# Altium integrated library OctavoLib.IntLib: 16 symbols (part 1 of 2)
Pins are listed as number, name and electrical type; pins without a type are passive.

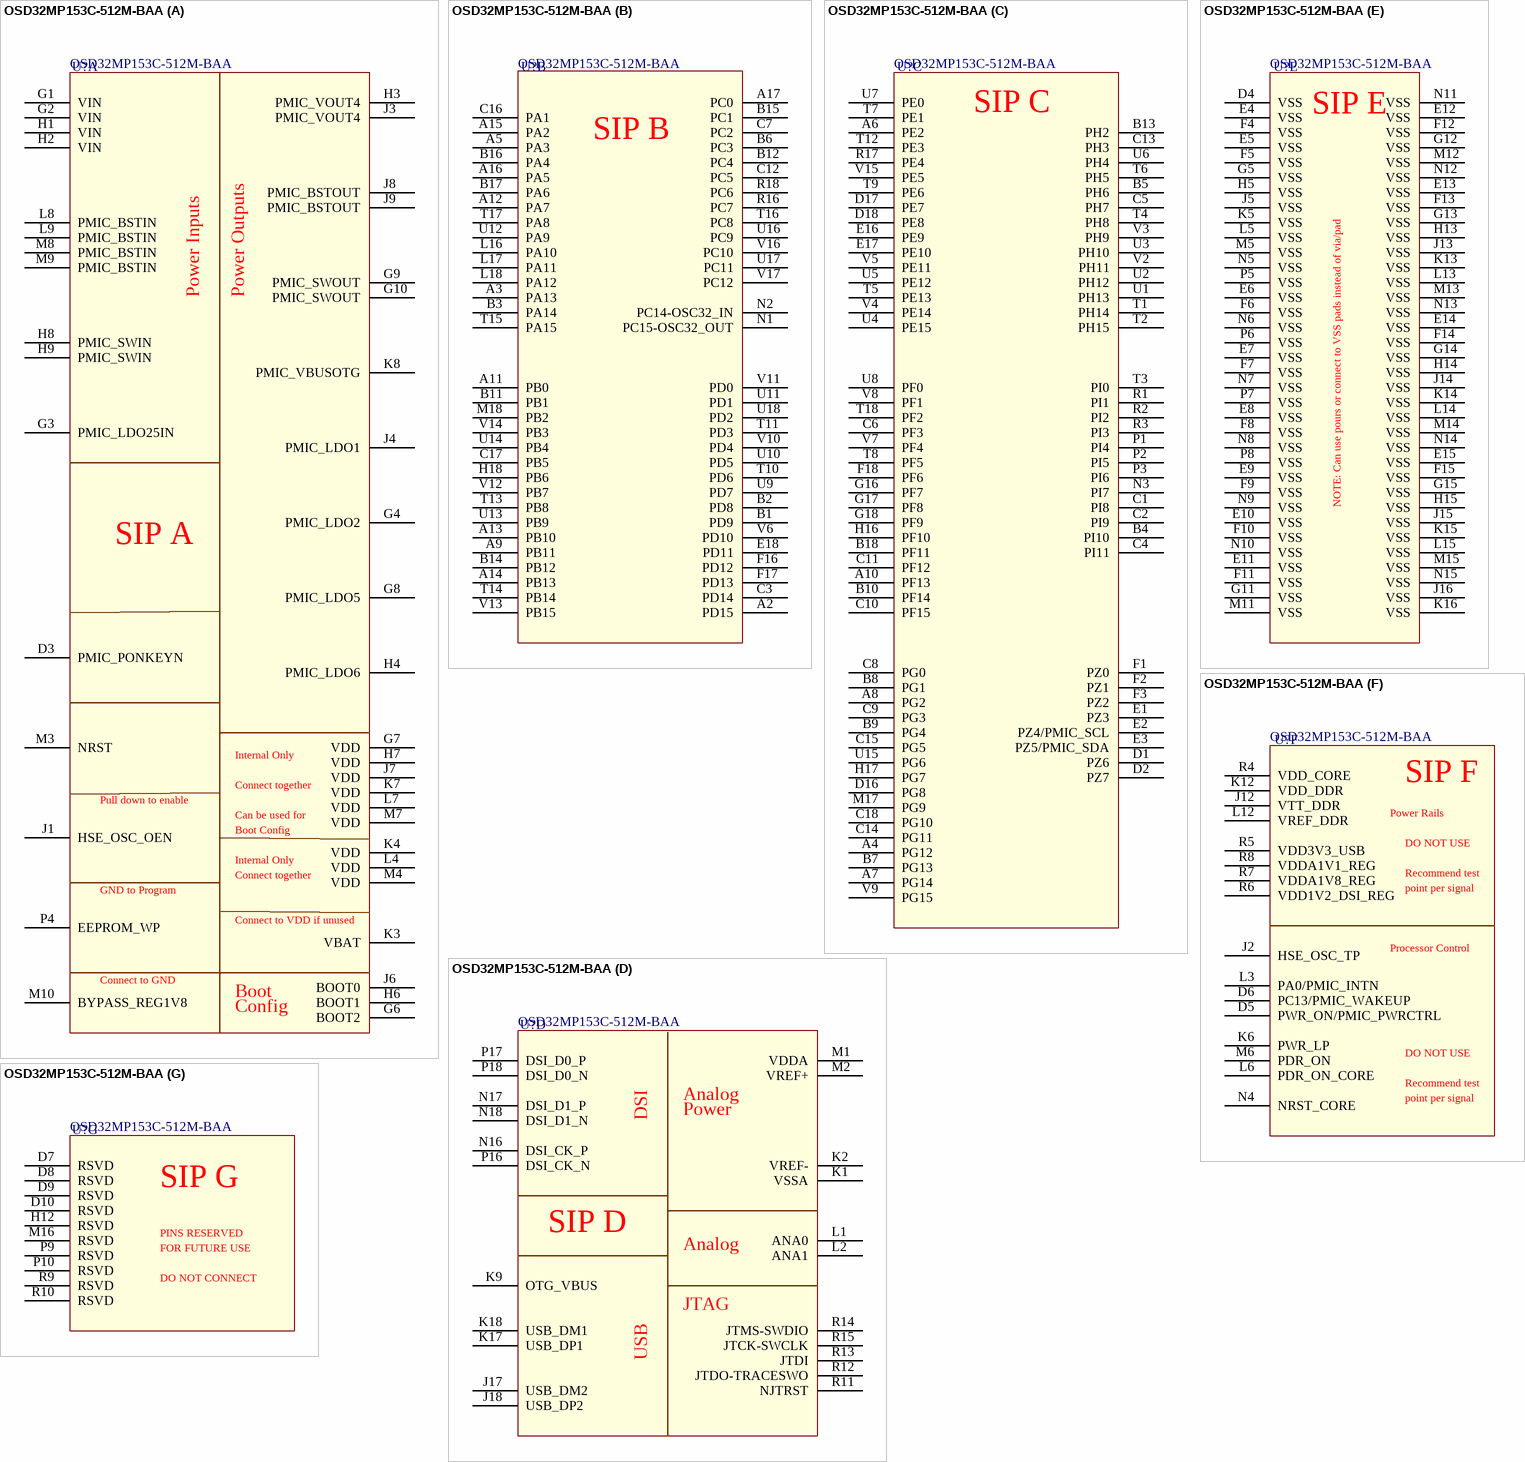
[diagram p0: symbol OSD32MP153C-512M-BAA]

## OSD32MP153C-512M-BAA
designator U?
Octavo Systems LLC OSD32MP15x Family SiP: 18mm x 18mm, 1mm pitch 302 pin BGA contains STM32MP153C, 512MB DDR3L, STPMIC1A, 4kB EEPROM, MEMS oscillators (24MHz) and passives. Commerical Temperature (case): 0C to 85C.
footprint BGA_18x18_302_1p00mm (302 pin 1mm pitch footprint)
part A pins: D3 PMIC_PONKEYN, G1 VIN, G2 VIN, G3 PMIC_LDO25IN, G4 PMIC_LDO2, G6 BOOT2, G7 VDD, G8 PMIC_LDO5, G9 PMIC_SWOUT, G10 PMIC_SWOUT, H1 VIN, H2 VIN, H3 PMIC_VOUT4, H4 PMIC_LDO6, H6 BOOT1, H7 VDD, H8 PMIC_SWIN, H9 PMIC_SWIN, J1 HSE_OSC_OEN, J3 PMIC_VOUT4, J4 PMIC_LDO1, J6 BOOT0, J7 VDD, J8 PMIC_BSTOUT, J9 PMIC_BSTOUT, K3 VBAT, K4 VDD, K7 VDD, K8 PMIC_VBUSOTG, L4 VDD, L7 VDD, L8 PMIC_BSTIN, L9 PMIC_BSTIN, M3 NRST, M4 VDD, M7 VDD, M8 PMIC_BSTIN, M9 PMIC_BSTIN, M10 BYPASS_REG1V8, P4 EEPROM_WP
part B pins: A2 PD15, A3 PA13, A5 PA3, A9 PB11, A11 PB0, A12 PA7, A13 PB10, A14 PB13, A15 PA2, A16 PA5, A17 PC0, B1 PD9, B2 PD8, B3 PA14, B6 PC3, B11 PB1, B12 PC4, B14 PB12, B15 PC1, B16 PA4, B17 PA6, C3 PD14, C7 PC2, C12 PC5, C16 PA1, C17 PB5, E18 PD11, F16 PD12, F17 PD13, H18 PB6, L16 PA10 "L16", L17 PA11, L18 PA12, M18 PB2, N1 PC15-OSC32_OUT, N2 PC14-OSC32_IN, R16 PC7, R18 PC6, T10 PD6, T11 PD3, T13 PB8, T14 PB14, T15 PA15, T16 PC8, T17 PA8, U9 PD7, U10 PD5, U11 PD1, U12 PA9, U13 PB9, U14 PB4, U16 PC9, U17 PC11, U18 PD2, V6 PD10, V10 PD4, V11 PD0, V12 PB7, V13 PB15, V14 PB3, V16 PC10, V17 PC12
part C pins: A4 PG12, A6 PE2, A7 PG14, A8 PG2, A10 PF13, B4 PI10, B5 PH6, B7 PG13, B8 PG1, B9 PG4, B10 PF14, B13 PH2, B18 PF11, C1 PI8, C2 PI9, C4 PI11, C5 PH7, C6 PF3, C8 PG0, C9 PG3, C10 PF15, C11 PF12, C13 PH3, C14 PG11, C15 PG5, C18 PG10, D1 PZ6, D2 PZ7, D16 PG8, D17 PE7, D18 PE8, E1 PZ3, E2 PZ4/PMIC_SCL, E3 PZ5/PMIC_SDA, E16 PE9, E17 PE10, F1 PZ0, F2 PZ1, F3 PZ2, F18 PF6, G16 PF7, G17 PF8, G18 PF9, H16 PF10, H17 PG7, M17 PG9, N3 PI7, P1 PI4, P2 PI5, P3 PI6, R1 PI1, R2 PI2, R3 PI3, R17 PE4, T1 PH14, T2 PH15, T3 PI0, T4 PH8, T5 PE13, T6 PH5, T7 PE1, T8 PF5, T9 PE6, T12 PE3, T18 PF2, U1 PH13, U2 PH12, U3 PH10, U4 PE15, U5 PE12, U6 PH4, U7 PE0, U8 PF0, U15 PG6, V2 PH11, V3 PH9, V4 PE14, V5 PE11, V7 PF4, V8 PF1, V9 PG15, V15 PE5
part D pins: J17 USB_DM2, J18 USB_DP2, K1 VSSA, K2 VREF-, K9 OTG_VBUS, K17 USB_DP1, K18 USB_DM1, L1 ANA0, L2 ANA1, M1 VDDA, M2 VREF+, N16 DSI_CK_P, N17 DSI_D1_P, N18 DSI_D1_N, P16 DSI_CK_N, P17 DSI_D0_P, P18 DSI_D0_N, R11 NJTRST, R12 JTDO-TRACESWO, R13 JTDI, R14 JTMS-SWDIO, R15 JTCK-SWCLK
part E pins: D4 VSS, E4 VSS, E5 VSS, E6 VSS, E7 VSS, E8 VSS, E9 VSS, E10 VSS, E11 VSS, E12 VSS, E13 VSS, E14 VSS, E15 VSS, F4 VSS, F5 VSS, F6 VSS, F7 VSS, F8 VSS, F9 VSS, F10 VSS, F11 VSS, F12 VSS, F13 VSS, F14 VSS, F15 VSS, G5 VSS, G11 VSS, G12 VSS, G13 VSS, G14 VSS, G15 VSS, H5 VSS, H13 VSS, H14 VSS, H15 VSS, J5 VSS, J13 VSS, J14 VSS, J15 VSS, J16 VSS, K5 VSS, K13 VSS, K14 VSS, K15 VSS, K16 VSS, L5 VSS, L13 VSS, L14 VSS, L15 VSS, M5 VSS, M11 VSS, M12 VSS, M13 VSS, M14 VSS, M15 VSS, N5 VSS, N6 VSS, N7 VSS, N8 VSS, N9 VSS, N10 VSS, N11 VSS, N12 VSS, N13 VSS, N14 VSS, N15 VSS, P5 VSS, P6 VSS, P7 VSS, P8 VSS
part F pins: D5 PWR_ON/PMIC_PWRCTRL, D6 PC13/PMIC_WAKEUP, J2 HSE_OSC_TP, J12 VTT_DDR, K6 PWR_LP, K12 VDD_DDR, L3 PA0/PMIC_INTN, L6 PDR_ON_CORE, L12 VREF_DDR, M6 PDR_ON, N4 NRST_CORE, R4 VDD_CORE, R5 VDD3V3_USB, R6 VDD1V2_DSI_REG, R7 VDDA1V8_REG, R8 VDDA1V1_REG
part G pins: D7 RSVD, D8 RSVD, D9 RSVD, D10 RSVD, H12 RSVD, M16 RSVD, P9 RSVD, P10 RSVD, R9 RSVD, R10 RSVD

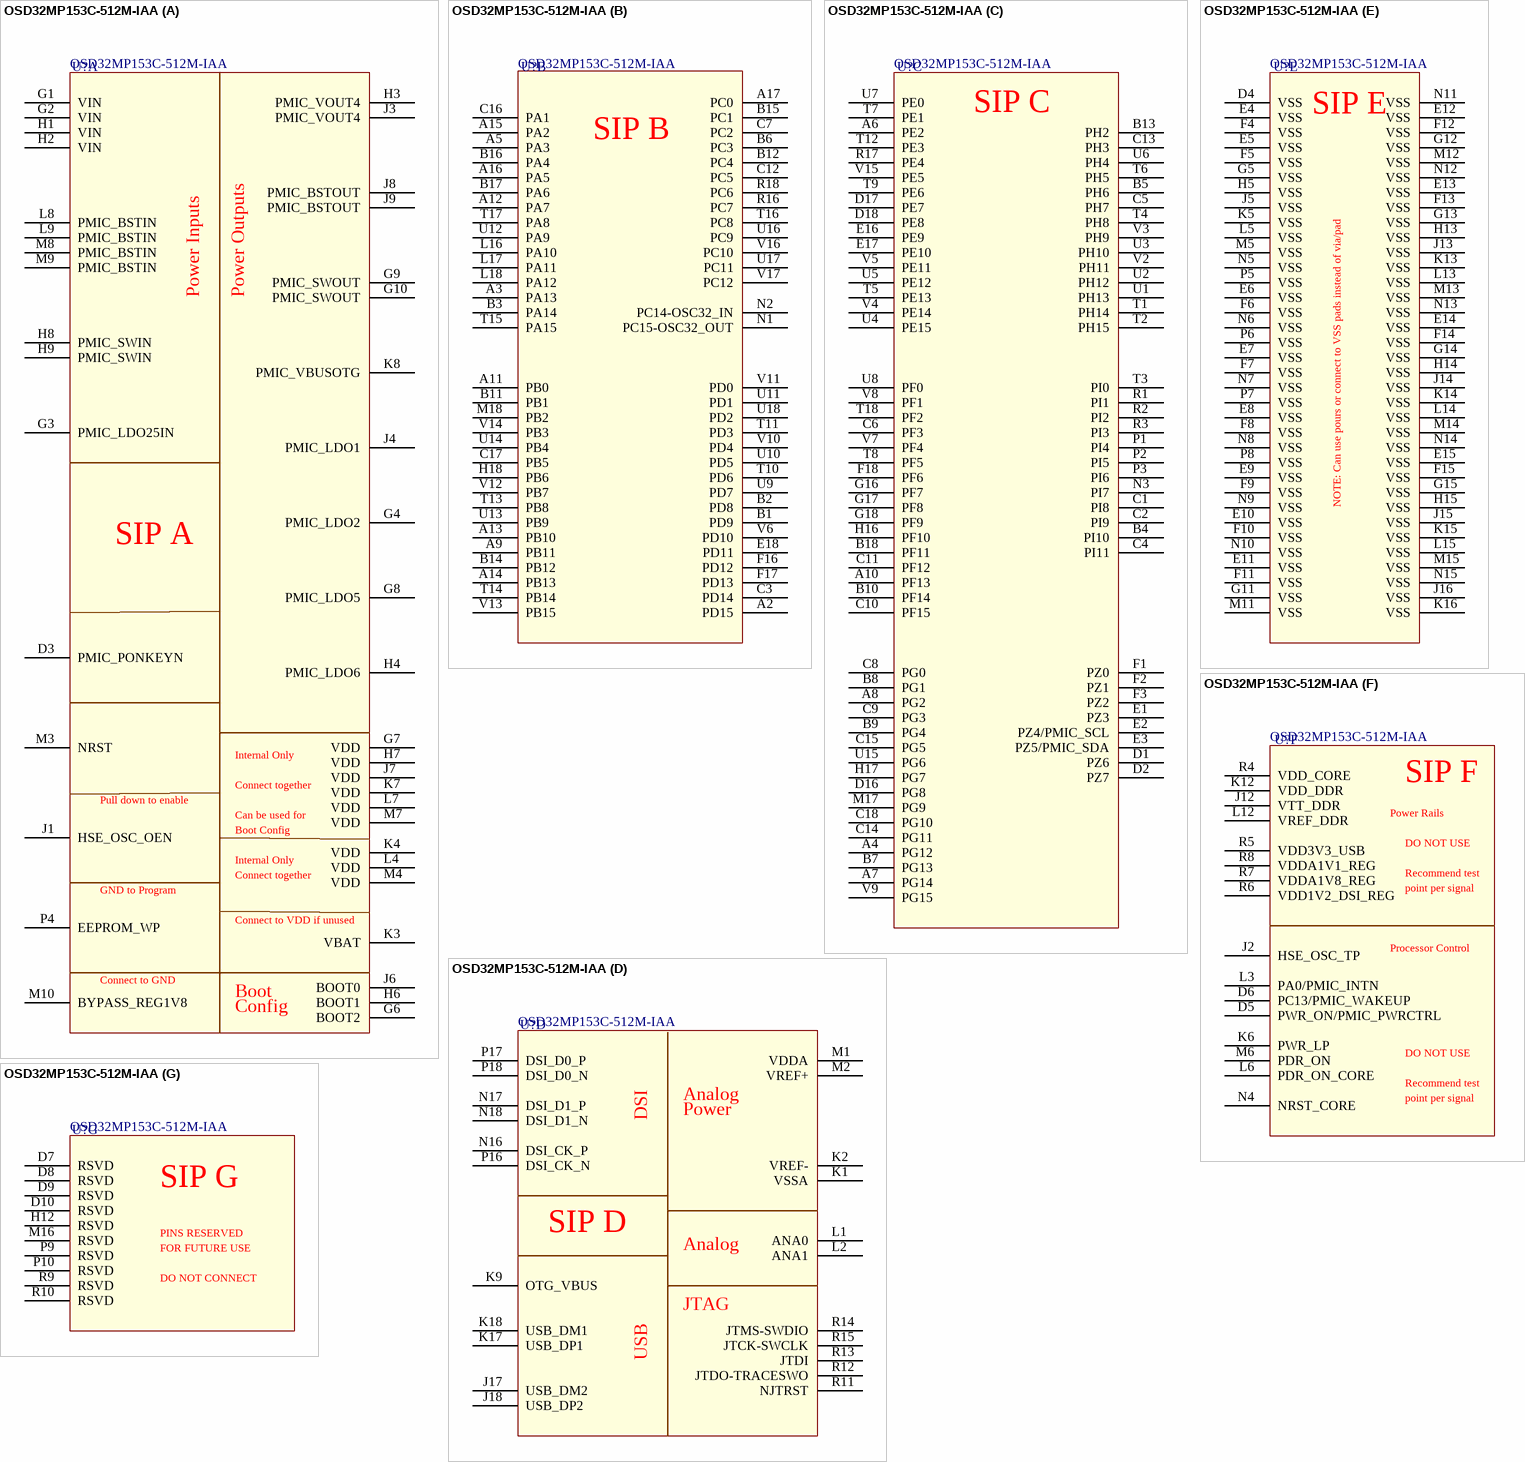
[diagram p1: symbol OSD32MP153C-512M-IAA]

## OSD32MP153C-512M-IAA
designator U?
Octavo Systems LLC OSD32MP15x Family SiP: 18mm x 18mm, 1mm pitch 302 pin BGA contains STM32MP153C, 512MB DDR3L, STPMIC1A, 4kB EEPROM, MEMS oscillators (24MHz) and passives. Industrial Temperature (case): -40C to 85C.
footprint BGA_18x18_302_1p00mm (302 pin 1mm pitch footprint)
part A pins: D3 PMIC_PONKEYN, G1 VIN, G2 VIN, G3 PMIC_LDO25IN, G4 PMIC_LDO2, G6 BOOT2, G7 VDD, G8 PMIC_LDO5, G9 PMIC_SWOUT, G10 PMIC_SWOUT, H1 VIN, H2 VIN, H3 PMIC_VOUT4, H4 PMIC_LDO6, H6 BOOT1, H7 VDD, H8 PMIC_SWIN, H9 PMIC_SWIN, J1 HSE_OSC_OEN, J3 PMIC_VOUT4, J4 PMIC_LDO1, J6 BOOT0, J7 VDD, J8 PMIC_BSTOUT, J9 PMIC_BSTOUT, K3 VBAT, K4 VDD, K7 VDD, K8 PMIC_VBUSOTG, L4 VDD, L7 VDD, L8 PMIC_BSTIN, L9 PMIC_BSTIN, M3 NRST, M4 VDD, M7 VDD, M8 PMIC_BSTIN, M9 PMIC_BSTIN, M10 BYPASS_REG1V8, P4 EEPROM_WP
part B pins: A2 PD15, A3 PA13, A5 PA3, A9 PB11, A11 PB0, A12 PA7, A13 PB10, A14 PB13, A15 PA2, A16 PA5, A17 PC0, B1 PD9, B2 PD8, B3 PA14, B6 PC3, B11 PB1, B12 PC4, B14 PB12, B15 PC1, B16 PA4, B17 PA6, C3 PD14, C7 PC2, C12 PC5, C16 PA1, C17 PB5, E18 PD11, F16 PD12, F17 PD13, H18 PB6, L16 PA10 "L16", L17 PA11, L18 PA12, M18 PB2, N1 PC15-OSC32_OUT, N2 PC14-OSC32_IN, R16 PC7, R18 PC6, T10 PD6, T11 PD3, T13 PB8, T14 PB14, T15 PA15, T16 PC8, T17 PA8, U9 PD7, U10 PD5, U11 PD1, U12 PA9, U13 PB9, U14 PB4, U16 PC9, U17 PC11, U18 PD2, V6 PD10, V10 PD4, V11 PD0, V12 PB7, V13 PB15, V14 PB3, V16 PC10, V17 PC12
part C pins: A4 PG12, A6 PE2, A7 PG14, A8 PG2, A10 PF13, B4 PI10, B5 PH6, B7 PG13, B8 PG1, B9 PG4, B10 PF14, B13 PH2, B18 PF11, C1 PI8, C2 PI9, C4 PI11, C5 PH7, C6 PF3, C8 PG0, C9 PG3, C10 PF15, C11 PF12, C13 PH3, C14 PG11, C15 PG5, C18 PG10, D1 PZ6, D2 PZ7, D16 PG8, D17 PE7, D18 PE8, E1 PZ3, E2 PZ4/PMIC_SCL, E3 PZ5/PMIC_SDA, E16 PE9, E17 PE10, F1 PZ0, F2 PZ1, F3 PZ2, F18 PF6, G16 PF7, G17 PF8, G18 PF9, H16 PF10, H17 PG7, M17 PG9, N3 PI7, P1 PI4, P2 PI5, P3 PI6, R1 PI1, R2 PI2, R3 PI3, R17 PE4, T1 PH14, T2 PH15, T3 PI0, T4 PH8, T5 PE13, T6 PH5, T7 PE1, T8 PF5, T9 PE6, T12 PE3, T18 PF2, U1 PH13, U2 PH12, U3 PH10, U4 PE15, U5 PE12, U6 PH4, U7 PE0, U8 PF0, U15 PG6, V2 PH11, V3 PH9, V4 PE14, V5 PE11, V7 PF4, V8 PF1, V9 PG15, V15 PE5
part D pins: J17 USB_DM2, J18 USB_DP2, K1 VSSA, K2 VREF-, K9 OTG_VBUS, K17 USB_DP1, K18 USB_DM1, L1 ANA0, L2 ANA1, M1 VDDA, M2 VREF+, N16 DSI_CK_P, N17 DSI_D1_P, N18 DSI_D1_N, P16 DSI_CK_N, P17 DSI_D0_P, P18 DSI_D0_N, R11 NJTRST, R12 JTDO-TRACESWO, R13 JTDI, R14 JTMS-SWDIO, R15 JTCK-SWCLK
part E pins: D4 VSS, E4 VSS, E5 VSS, E6 VSS, E7 VSS, E8 VSS, E9 VSS, E10 VSS, E11 VSS, E12 VSS, E13 VSS, E14 VSS, E15 VSS, F4 VSS, F5 VSS, F6 VSS, F7 VSS, F8 VSS, F9 VSS, F10 VSS, F11 VSS, F12 VSS, F13 VSS, F14 VSS, F15 VSS, G5 VSS, G11 VSS, G12 VSS, G13 VSS, G14 VSS, G15 VSS, H5 VSS, H13 VSS, H14 VSS, H15 VSS, J5 VSS, J13 VSS, J14 VSS, J15 VSS, J16 VSS, K5 VSS, K13 VSS, K14 VSS, K15 VSS, K16 VSS, L5 VSS, L13 VSS, L14 VSS, L15 VSS, M5 VSS, M11 VSS, M12 VSS, M13 VSS, M14 VSS, M15 VSS, N5 VSS, N6 VSS, N7 VSS, N8 VSS, N9 VSS, N10 VSS, N11 VSS, N12 VSS, N13 VSS, N14 VSS, N15 VSS, P5 VSS, P6 VSS, P7 VSS, P8 VSS
part F pins: D5 PWR_ON/PMIC_PWRCTRL, D6 PC13/PMIC_WAKEUP, J2 HSE_OSC_TP, J12 VTT_DDR, K6 PWR_LP, K12 VDD_DDR, L3 PA0/PMIC_INTN, L6 PDR_ON_CORE, L12 VREF_DDR, M6 PDR_ON, N4 NRST_CORE, R4 VDD_CORE, R5 VDD3V3_USB, R6 VDD1V2_DSI_REG, R7 VDDA1V8_REG, R8 VDDA1V1_REG
part G pins: D7 RSVD, D8 RSVD, D9 RSVD, D10 RSVD, H12 RSVD, M16 RSVD, P9 RSVD, P10 RSVD, R9 RSVD, R10 RSVD

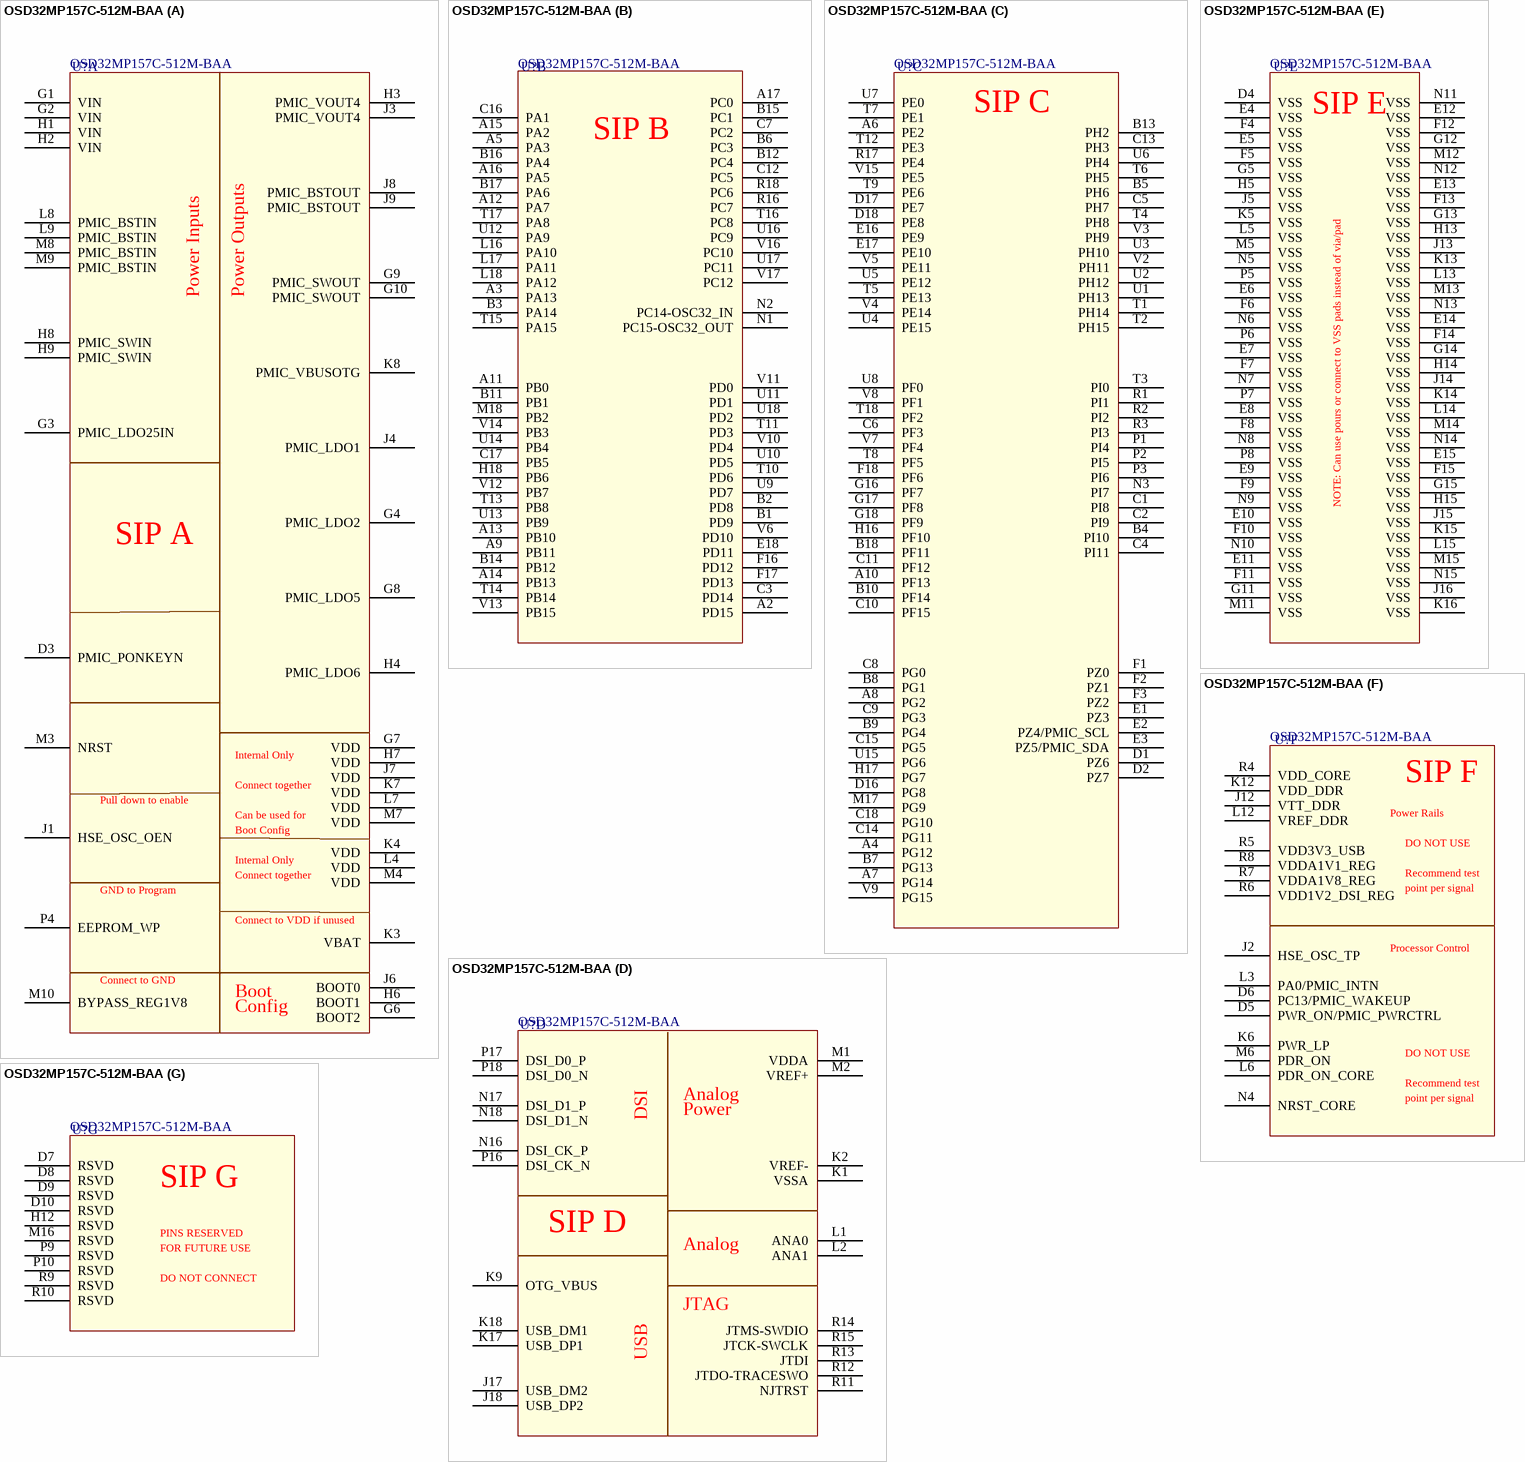
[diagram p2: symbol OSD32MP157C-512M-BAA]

## OSD32MP157C-512M-BAA
designator U?
Octavo Systems LLC OSD32MP15x Family SiP: 18mm x 18mm, 1mm pitch 302 pin BGA contains STM32MP157C, 512MB DDR3L, STPMIC1A, 4kB EEPROM, MEMS oscillators (24MHz) and passives. Commerical Temperature (case): 0C to 85C.
footprint BGA_18x18_302_1p00mm (302 pin 1mm pitch footprint)
part A pins: D3 PMIC_PONKEYN, G1 VIN, G2 VIN, G3 PMIC_LDO25IN, G4 PMIC_LDO2, G6 BOOT2, G7 VDD, G8 PMIC_LDO5, G9 PMIC_SWOUT, G10 PMIC_SWOUT, H1 VIN, H2 VIN, H3 PMIC_VOUT4, H4 PMIC_LDO6, H6 BOOT1, H7 VDD, H8 PMIC_SWIN, H9 PMIC_SWIN, J1 HSE_OSC_OEN, J3 PMIC_VOUT4, J4 PMIC_LDO1, J6 BOOT0, J7 VDD, J8 PMIC_BSTOUT, J9 PMIC_BSTOUT, K3 VBAT, K4 VDD, K7 VDD, K8 PMIC_VBUSOTG, L4 VDD, L7 VDD, L8 PMIC_BSTIN, L9 PMIC_BSTIN, M3 NRST, M4 VDD, M7 VDD, M8 PMIC_BSTIN, M9 PMIC_BSTIN, M10 BYPASS_REG1V8, P4 EEPROM_WP
part B pins: A2 PD15, A3 PA13, A5 PA3, A9 PB11, A11 PB0, A12 PA7, A13 PB10, A14 PB13, A15 PA2, A16 PA5, A17 PC0, B1 PD9, B2 PD8, B3 PA14, B6 PC3, B11 PB1, B12 PC4, B14 PB12, B15 PC1, B16 PA4, B17 PA6, C3 PD14, C7 PC2, C12 PC5, C16 PA1, C17 PB5, E18 PD11, F16 PD12, F17 PD13, H18 PB6, L16 PA10 "L16", L17 PA11, L18 PA12, M18 PB2, N1 PC15-OSC32_OUT, N2 PC14-OSC32_IN, R16 PC7, R18 PC6, T10 PD6, T11 PD3, T13 PB8, T14 PB14, T15 PA15, T16 PC8, T17 PA8, U9 PD7, U10 PD5, U11 PD1, U12 PA9, U13 PB9, U14 PB4, U16 PC9, U17 PC11, U18 PD2, V6 PD10, V10 PD4, V11 PD0, V12 PB7, V13 PB15, V14 PB3, V16 PC10, V17 PC12
part C pins: A4 PG12, A6 PE2, A7 PG14, A8 PG2, A10 PF13, B4 PI10, B5 PH6, B7 PG13, B8 PG1, B9 PG4, B10 PF14, B13 PH2, B18 PF11, C1 PI8, C2 PI9, C4 PI11, C5 PH7, C6 PF3, C8 PG0, C9 PG3, C10 PF15, C11 PF12, C13 PH3, C14 PG11, C15 PG5, C18 PG10, D1 PZ6, D2 PZ7, D16 PG8, D17 PE7, D18 PE8, E1 PZ3, E2 PZ4/PMIC_SCL, E3 PZ5/PMIC_SDA, E16 PE9, E17 PE10, F1 PZ0, F2 PZ1, F3 PZ2, F18 PF6, G16 PF7, G17 PF8, G18 PF9, H16 PF10, H17 PG7, M17 PG9, N3 PI7, P1 PI4, P2 PI5, P3 PI6, R1 PI1, R2 PI2, R3 PI3, R17 PE4, T1 PH14, T2 PH15, T3 PI0, T4 PH8, T5 PE13, T6 PH5, T7 PE1, T8 PF5, T9 PE6, T12 PE3, T18 PF2, U1 PH13, U2 PH12, U3 PH10, U4 PE15, U5 PE12, U6 PH4, U7 PE0, U8 PF0, U15 PG6, V2 PH11, V3 PH9, V4 PE14, V5 PE11, V7 PF4, V8 PF1, V9 PG15, V15 PE5
part D pins: J17 USB_DM2, J18 USB_DP2, K1 VSSA, K2 VREF-, K9 OTG_VBUS, K17 USB_DP1, K18 USB_DM1, L1 ANA0, L2 ANA1, M1 VDDA, M2 VREF+, N16 DSI_CK_P, N17 DSI_D1_P, N18 DSI_D1_N, P16 DSI_CK_N, P17 DSI_D0_P, P18 DSI_D0_N, R11 NJTRST, R12 JTDO-TRACESWO, R13 JTDI, R14 JTMS-SWDIO, R15 JTCK-SWCLK
part E pins: D4 VSS, E4 VSS, E5 VSS, E6 VSS, E7 VSS, E8 VSS, E9 VSS, E10 VSS, E11 VSS, E12 VSS, E13 VSS, E14 VSS, E15 VSS, F4 VSS, F5 VSS, F6 VSS, F7 VSS, F8 VSS, F9 VSS, F10 VSS, F11 VSS, F12 VSS, F13 VSS, F14 VSS, F15 VSS, G5 VSS, G11 VSS, G12 VSS, G13 VSS, G14 VSS, G15 VSS, H5 VSS, H13 VSS, H14 VSS, H15 VSS, J5 VSS, J13 VSS, J14 VSS, J15 VSS, J16 VSS, K5 VSS, K13 VSS, K14 VSS, K15 VSS, K16 VSS, L5 VSS, L13 VSS, L14 VSS, L15 VSS, M5 VSS, M11 VSS, M12 VSS, M13 VSS, M14 VSS, M15 VSS, N5 VSS, N6 VSS, N7 VSS, N8 VSS, N9 VSS, N10 VSS, N11 VSS, N12 VSS, N13 VSS, N14 VSS, N15 VSS, P5 VSS, P6 VSS, P7 VSS, P8 VSS
part F pins: D5 PWR_ON/PMIC_PWRCTRL, D6 PC13/PMIC_WAKEUP, J2 HSE_OSC_TP, J12 VTT_DDR, K6 PWR_LP, K12 VDD_DDR, L3 PA0/PMIC_INTN, L6 PDR_ON_CORE, L12 VREF_DDR, M6 PDR_ON, N4 NRST_CORE, R4 VDD_CORE, R5 VDD3V3_USB, R6 VDD1V2_DSI_REG, R7 VDDA1V8_REG, R8 VDDA1V1_REG
part G pins: D7 RSVD, D8 RSVD, D9 RSVD, D10 RSVD, H12 RSVD, M16 RSVD, P9 RSVD, P10 RSVD, R9 RSVD, R10 RSVD

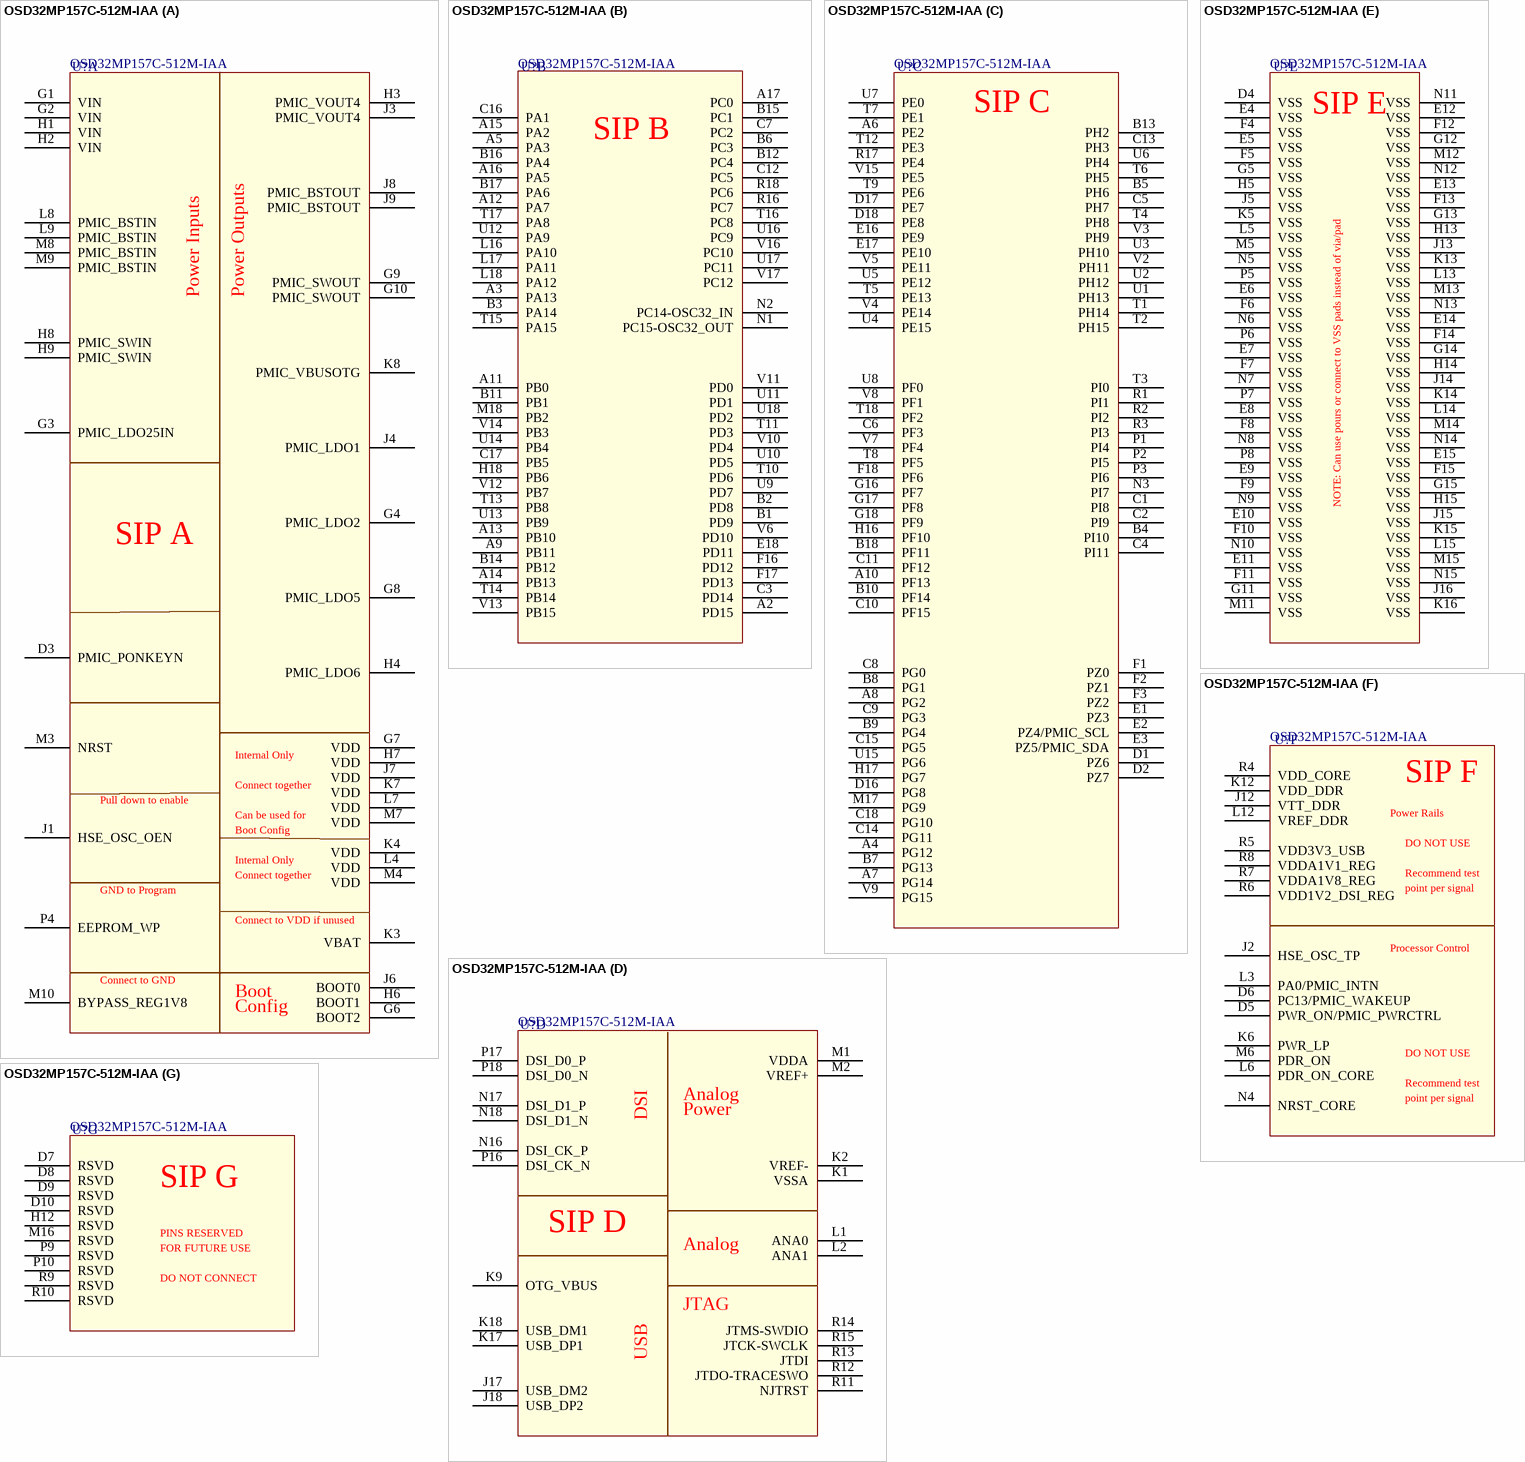
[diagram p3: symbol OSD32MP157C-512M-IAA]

## OSD32MP157C-512M-IAA
designator U?
Octavo Systems LLC OSD32MP15x Family SiP: 18mm x 18mm, 1mm pitch 302 pin BGA contains STM32MP157C, 512MB DDR3L, STPMIC1A, 4kB EEPROM, MEMS oscillators (24MHz) and passives. Industrial Temperature (case): -40C to 85C.
footprint BGA_18x18_302_1p00mm (302 pin 1mm pitch footprint)
part A pins: D3 PMIC_PONKEYN, G1 VIN, G2 VIN, G3 PMIC_LDO25IN, G4 PMIC_LDO2, G6 BOOT2, G7 VDD, G8 PMIC_LDO5, G9 PMIC_SWOUT, G10 PMIC_SWOUT, H1 VIN, H2 VIN, H3 PMIC_VOUT4, H4 PMIC_LDO6, H6 BOOT1, H7 VDD, H8 PMIC_SWIN, H9 PMIC_SWIN, J1 HSE_OSC_OEN, J3 PMIC_VOUT4, J4 PMIC_LDO1, J6 BOOT0, J7 VDD, J8 PMIC_BSTOUT, J9 PMIC_BSTOUT, K3 VBAT, K4 VDD, K7 VDD, K8 PMIC_VBUSOTG, L4 VDD, L7 VDD, L8 PMIC_BSTIN, L9 PMIC_BSTIN, M3 NRST, M4 VDD, M7 VDD, M8 PMIC_BSTIN, M9 PMIC_BSTIN, M10 BYPASS_REG1V8, P4 EEPROM_WP
part B pins: A2 PD15, A3 PA13, A5 PA3, A9 PB11, A11 PB0, A12 PA7, A13 PB10, A14 PB13, A15 PA2, A16 PA5, A17 PC0, B1 PD9, B2 PD8, B3 PA14, B6 PC3, B11 PB1, B12 PC4, B14 PB12, B15 PC1, B16 PA4, B17 PA6, C3 PD14, C7 PC2, C12 PC5, C16 PA1, C17 PB5, E18 PD11, F16 PD12, F17 PD13, H18 PB6, L16 PA10 "L16", L17 PA11, L18 PA12, M18 PB2, N1 PC15-OSC32_OUT, N2 PC14-OSC32_IN, R16 PC7, R18 PC6, T10 PD6, T11 PD3, T13 PB8, T14 PB14, T15 PA15, T16 PC8, T17 PA8, U9 PD7, U10 PD5, U11 PD1, U12 PA9, U13 PB9, U14 PB4, U16 PC9, U17 PC11, U18 PD2, V6 PD10, V10 PD4, V11 PD0, V12 PB7, V13 PB15, V14 PB3, V16 PC10, V17 PC12
part C pins: A4 PG12, A6 PE2, A7 PG14, A8 PG2, A10 PF13, B4 PI10, B5 PH6, B7 PG13, B8 PG1, B9 PG4, B10 PF14, B13 PH2, B18 PF11, C1 PI8, C2 PI9, C4 PI11, C5 PH7, C6 PF3, C8 PG0, C9 PG3, C10 PF15, C11 PF12, C13 PH3, C14 PG11, C15 PG5, C18 PG10, D1 PZ6, D2 PZ7, D16 PG8, D17 PE7, D18 PE8, E1 PZ3, E2 PZ4/PMIC_SCL, E3 PZ5/PMIC_SDA, E16 PE9, E17 PE10, F1 PZ0, F2 PZ1, F3 PZ2, F18 PF6, G16 PF7, G17 PF8, G18 PF9, H16 PF10, H17 PG7, M17 PG9, N3 PI7, P1 PI4, P2 PI5, P3 PI6, R1 PI1, R2 PI2, R3 PI3, R17 PE4, T1 PH14, T2 PH15, T3 PI0, T4 PH8, T5 PE13, T6 PH5, T7 PE1, T8 PF5, T9 PE6, T12 PE3, T18 PF2, U1 PH13, U2 PH12, U3 PH10, U4 PE15, U5 PE12, U6 PH4, U7 PE0, U8 PF0, U15 PG6, V2 PH11, V3 PH9, V4 PE14, V5 PE11, V7 PF4, V8 PF1, V9 PG15, V15 PE5
part D pins: J17 USB_DM2, J18 USB_DP2, K1 VSSA, K2 VREF-, K9 OTG_VBUS, K17 USB_DP1, K18 USB_DM1, L1 ANA0, L2 ANA1, M1 VDDA, M2 VREF+, N16 DSI_CK_P, N17 DSI_D1_P, N18 DSI_D1_N, P16 DSI_CK_N, P17 DSI_D0_P, P18 DSI_D0_N, R11 NJTRST, R12 JTDO-TRACESWO, R13 JTDI, R14 JTMS-SWDIO, R15 JTCK-SWCLK
part E pins: D4 VSS, E4 VSS, E5 VSS, E6 VSS, E7 VSS, E8 VSS, E9 VSS, E10 VSS, E11 VSS, E12 VSS, E13 VSS, E14 VSS, E15 VSS, F4 VSS, F5 VSS, F6 VSS, F7 VSS, F8 VSS, F9 VSS, F10 VSS, F11 VSS, F12 VSS, F13 VSS, F14 VSS, F15 VSS, G5 VSS, G11 VSS, G12 VSS, G13 VSS, G14 VSS, G15 VSS, H5 VSS, H13 VSS, H14 VSS, H15 VSS, J5 VSS, J13 VSS, J14 VSS, J15 VSS, J16 VSS, K5 VSS, K13 VSS, K14 VSS, K15 VSS, K16 VSS, L5 VSS, L13 VSS, L14 VSS, L15 VSS, M5 VSS, M11 VSS, M12 VSS, M13 VSS, M14 VSS, M15 VSS, N5 VSS, N6 VSS, N7 VSS, N8 VSS, N9 VSS, N10 VSS, N11 VSS, N12 VSS, N13 VSS, N14 VSS, N15 VSS, P5 VSS, P6 VSS, P7 VSS, P8 VSS
part F pins: D5 PWR_ON/PMIC_PWRCTRL, D6 PC13/PMIC_WAKEUP, J2 HSE_OSC_TP, J12 VTT_DDR, K6 PWR_LP, K12 VDD_DDR, L3 PA0/PMIC_INTN, L6 PDR_ON_CORE, L12 VREF_DDR, M6 PDR_ON, N4 NRST_CORE, R4 VDD_CORE, R5 VDD3V3_USB, R6 VDD1V2_DSI_REG, R7 VDDA1V8_REG, R8 VDDA1V1_REG
part G pins: D7 RSVD, D8 RSVD, D9 RSVD, D10 RSVD, H12 RSVD, M16 RSVD, P9 RSVD, P10 RSVD, R9 RSVD, R10 RSVD

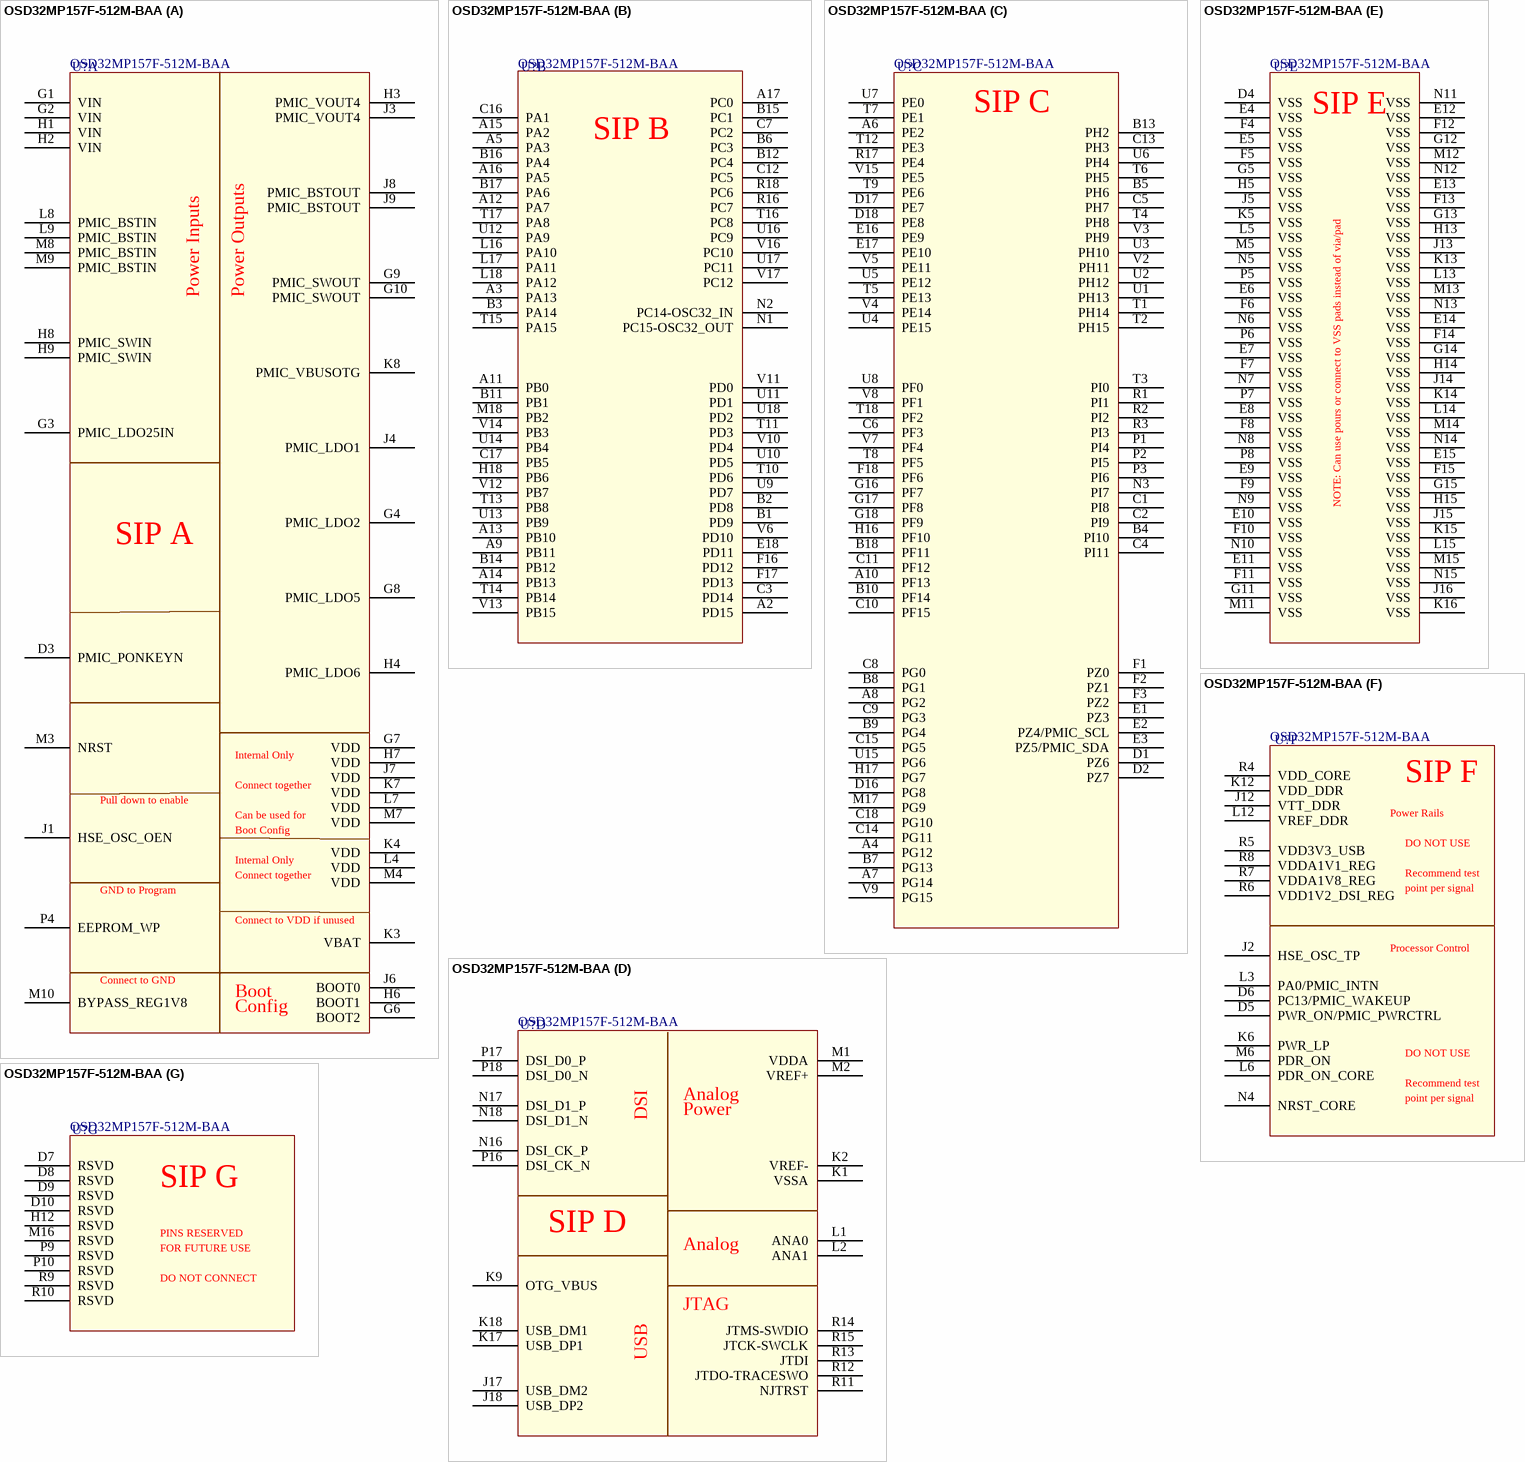
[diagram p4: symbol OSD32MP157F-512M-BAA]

## OSD32MP157F-512M-BAA
designator U?
Octavo Systems LLC OSD32MP15x Family SiP: 18mm x 18mm, 1mm pitch 302 pin BGA contains STM32MP157F, 512MB DDR3L, STPMIC1A, 4kB EEPROM, MEMS oscillators (24MHz) and passives. Commerical Temperature (case): 0C to 85C.
footprint BGA_18x18_302_1p00mm (302 pin 1mm pitch footprint)
part A pins: D3 PMIC_PONKEYN, G1 VIN, G2 VIN, G3 PMIC_LDO25IN, G4 PMIC_LDO2, G6 BOOT2, G7 VDD, G8 PMIC_LDO5, G9 PMIC_SWOUT, G10 PMIC_SWOUT, H1 VIN, H2 VIN, H3 PMIC_VOUT4, H4 PMIC_LDO6, H6 BOOT1, H7 VDD, H8 PMIC_SWIN, H9 PMIC_SWIN, J1 HSE_OSC_OEN, J3 PMIC_VOUT4, J4 PMIC_LDO1, J6 BOOT0, J7 VDD, J8 PMIC_BSTOUT, J9 PMIC_BSTOUT, K3 VBAT, K4 VDD, K7 VDD, K8 PMIC_VBUSOTG, L4 VDD, L7 VDD, L8 PMIC_BSTIN, L9 PMIC_BSTIN, M3 NRST, M4 VDD, M7 VDD, M8 PMIC_BSTIN, M9 PMIC_BSTIN, M10 BYPASS_REG1V8, P4 EEPROM_WP
part B pins: A2 PD15, A3 PA13, A5 PA3, A9 PB11, A11 PB0, A12 PA7, A13 PB10, A14 PB13, A15 PA2, A16 PA5, A17 PC0, B1 PD9, B2 PD8, B3 PA14, B6 PC3, B11 PB1, B12 PC4, B14 PB12, B15 PC1, B16 PA4, B17 PA6, C3 PD14, C7 PC2, C12 PC5, C16 PA1, C17 PB5, E18 PD11, F16 PD12, F17 PD13, H18 PB6, L16 PA10 "L16", L17 PA11, L18 PA12, M18 PB2, N1 PC15-OSC32_OUT, N2 PC14-OSC32_IN, R16 PC7, R18 PC6, T10 PD6, T11 PD3, T13 PB8, T14 PB14, T15 PA15, T16 PC8, T17 PA8, U9 PD7, U10 PD5, U11 PD1, U12 PA9, U13 PB9, U14 PB4, U16 PC9, U17 PC11, U18 PD2, V6 PD10, V10 PD4, V11 PD0, V12 PB7, V13 PB15, V14 PB3, V16 PC10, V17 PC12
part C pins: A4 PG12, A6 PE2, A7 PG14, A8 PG2, A10 PF13, B4 PI10, B5 PH6, B7 PG13, B8 PG1, B9 PG4, B10 PF14, B13 PH2, B18 PF11, C1 PI8, C2 PI9, C4 PI11, C5 PH7, C6 PF3, C8 PG0, C9 PG3, C10 PF15, C11 PF12, C13 PH3, C14 PG11, C15 PG5, C18 PG10, D1 PZ6, D2 PZ7, D16 PG8, D17 PE7, D18 PE8, E1 PZ3, E2 PZ4/PMIC_SCL, E3 PZ5/PMIC_SDA, E16 PE9, E17 PE10, F1 PZ0, F2 PZ1, F3 PZ2, F18 PF6, G16 PF7, G17 PF8, G18 PF9, H16 PF10, H17 PG7, M17 PG9, N3 PI7, P1 PI4, P2 PI5, P3 PI6, R1 PI1, R2 PI2, R3 PI3, R17 PE4, T1 PH14, T2 PH15, T3 PI0, T4 PH8, T5 PE13, T6 PH5, T7 PE1, T8 PF5, T9 PE6, T12 PE3, T18 PF2, U1 PH13, U2 PH12, U3 PH10, U4 PE15, U5 PE12, U6 PH4, U7 PE0, U8 PF0, U15 PG6, V2 PH11, V3 PH9, V4 PE14, V5 PE11, V7 PF4, V8 PF1, V9 PG15, V15 PE5
part D pins: J17 USB_DM2, J18 USB_DP2, K1 VSSA, K2 VREF-, K9 OTG_VBUS, K17 USB_DP1, K18 USB_DM1, L1 ANA0, L2 ANA1, M1 VDDA, M2 VREF+, N16 DSI_CK_P, N17 DSI_D1_P, N18 DSI_D1_N, P16 DSI_CK_N, P17 DSI_D0_P, P18 DSI_D0_N, R11 NJTRST, R12 JTDO-TRACESWO, R13 JTDI, R14 JTMS-SWDIO, R15 JTCK-SWCLK
part E pins: D4 VSS, E4 VSS, E5 VSS, E6 VSS, E7 VSS, E8 VSS, E9 VSS, E10 VSS, E11 VSS, E12 VSS, E13 VSS, E14 VSS, E15 VSS, F4 VSS, F5 VSS, F6 VSS, F7 VSS, F8 VSS, F9 VSS, F10 VSS, F11 VSS, F12 VSS, F13 VSS, F14 VSS, F15 VSS, G5 VSS, G11 VSS, G12 VSS, G13 VSS, G14 VSS, G15 VSS, H5 VSS, H13 VSS, H14 VSS, H15 VSS, J5 VSS, J13 VSS, J14 VSS, J15 VSS, J16 VSS, K5 VSS, K13 VSS, K14 VSS, K15 VSS, K16 VSS, L5 VSS, L13 VSS, L14 VSS, L15 VSS, M5 VSS, M11 VSS, M12 VSS, M13 VSS, M14 VSS, M15 VSS, N5 VSS, N6 VSS, N7 VSS, N8 VSS, N9 VSS, N10 VSS, N11 VSS, N12 VSS, N13 VSS, N14 VSS, N15 VSS, P5 VSS, P6 VSS, P7 VSS, P8 VSS
part F pins: D5 PWR_ON/PMIC_PWRCTRL, D6 PC13/PMIC_WAKEUP, J2 HSE_OSC_TP, J12 VTT_DDR, K6 PWR_LP, K12 VDD_DDR, L3 PA0/PMIC_INTN, L6 PDR_ON_CORE, L12 VREF_DDR, M6 PDR_ON, N4 NRST_CORE, R4 VDD_CORE, R5 VDD3V3_USB, R6 VDD1V2_DSI_REG, R7 VDDA1V8_REG, R8 VDDA1V1_REG
part G pins: D7 RSVD, D8 RSVD, D9 RSVD, D10 RSVD, H12 RSVD, M16 RSVD, P9 RSVD, P10 RSVD, R9 RSVD, R10 RSVD

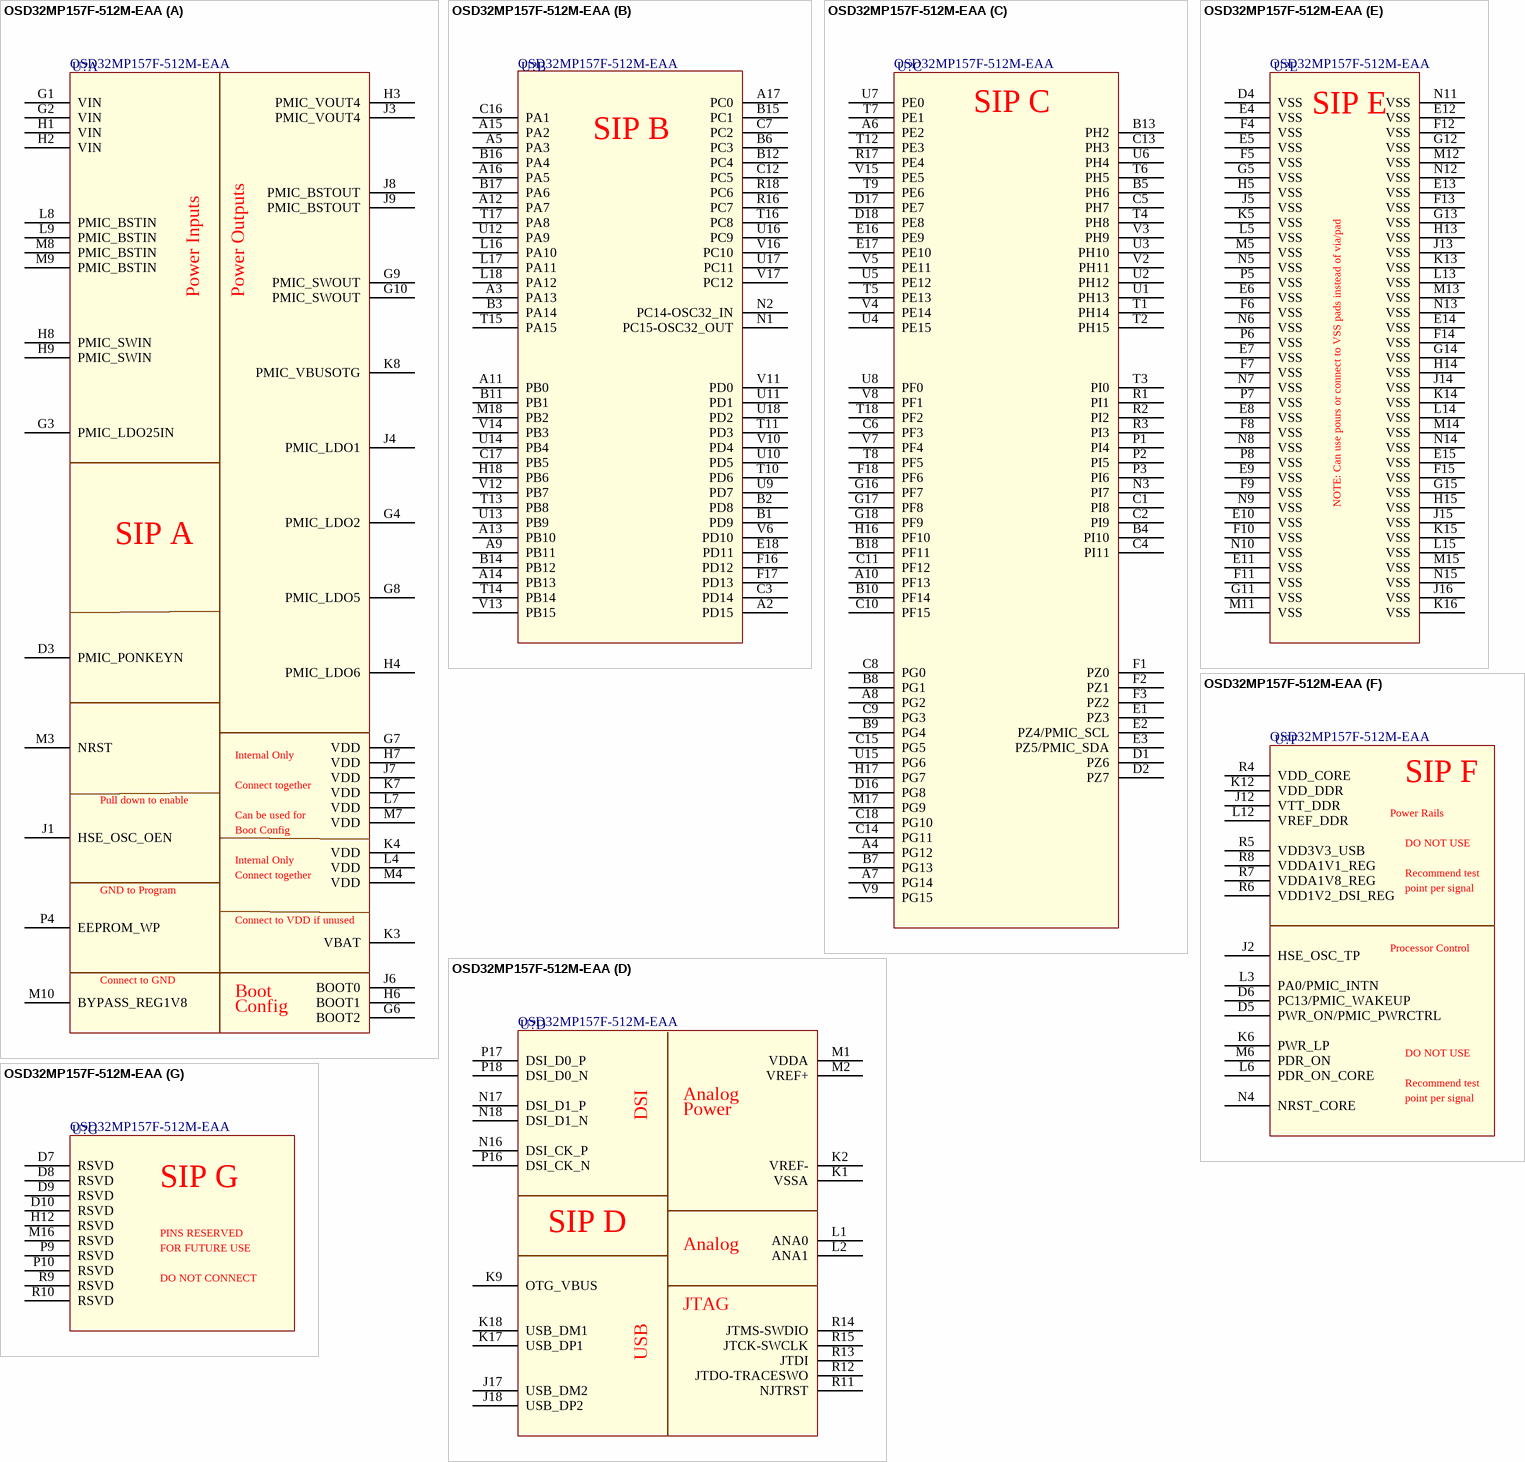
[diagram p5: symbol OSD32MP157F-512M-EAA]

## OSD32MP157F-512M-EAA
designator U?
Octavo Systems LLC OSD32MP15x Family SiP: 18mm x 18mm, 1mm pitch 302 pin BGA contains STM32MP157F, 512MB DDR3L, STPMIC1A, 4kB EEPROM, MEMS oscillators (24MHz) and passives. Temperature range (case): -20C to 85C.
footprint BGA_18x18_302_1p00mm (302 pin 1mm pitch footprint)
part A pins: D3 PMIC_PONKEYN, G1 VIN, G2 VIN, G3 PMIC_LDO25IN, G4 PMIC_LDO2, G6 BOOT2, G7 VDD, G8 PMIC_LDO5, G9 PMIC_SWOUT, G10 PMIC_SWOUT, H1 VIN, H2 VIN, H3 PMIC_VOUT4, H4 PMIC_LDO6, H6 BOOT1, H7 VDD, H8 PMIC_SWIN, H9 PMIC_SWIN, J1 HSE_OSC_OEN, J3 PMIC_VOUT4, J4 PMIC_LDO1, J6 BOOT0, J7 VDD, J8 PMIC_BSTOUT, J9 PMIC_BSTOUT, K3 VBAT, K4 VDD, K7 VDD, K8 PMIC_VBUSOTG, L4 VDD, L7 VDD, L8 PMIC_BSTIN, L9 PMIC_BSTIN, M3 NRST, M4 VDD, M7 VDD, M8 PMIC_BSTIN, M9 PMIC_BSTIN, M10 BYPASS_REG1V8, P4 EEPROM_WP
part B pins: A2 PD15, A3 PA13, A5 PA3, A9 PB11, A11 PB0, A12 PA7, A13 PB10, A14 PB13, A15 PA2, A16 PA5, A17 PC0, B1 PD9, B2 PD8, B3 PA14, B6 PC3, B11 PB1, B12 PC4, B14 PB12, B15 PC1, B16 PA4, B17 PA6, C3 PD14, C7 PC2, C12 PC5, C16 PA1, C17 PB5, E18 PD11, F16 PD12, F17 PD13, H18 PB6, L16 PA10 "L16", L17 PA11, L18 PA12, M18 PB2, N1 PC15-OSC32_OUT, N2 PC14-OSC32_IN, R16 PC7, R18 PC6, T10 PD6, T11 PD3, T13 PB8, T14 PB14, T15 PA15, T16 PC8, T17 PA8, U9 PD7, U10 PD5, U11 PD1, U12 PA9, U13 PB9, U14 PB4, U16 PC9, U17 PC11, U18 PD2, V6 PD10, V10 PD4, V11 PD0, V12 PB7, V13 PB15, V14 PB3, V16 PC10, V17 PC12
part C pins: A4 PG12, A6 PE2, A7 PG14, A8 PG2, A10 PF13, B4 PI10, B5 PH6, B7 PG13, B8 PG1, B9 PG4, B10 PF14, B13 PH2, B18 PF11, C1 PI8, C2 PI9, C4 PI11, C5 PH7, C6 PF3, C8 PG0, C9 PG3, C10 PF15, C11 PF12, C13 PH3, C14 PG11, C15 PG5, C18 PG10, D1 PZ6, D2 PZ7, D16 PG8, D17 PE7, D18 PE8, E1 PZ3, E2 PZ4/PMIC_SCL, E3 PZ5/PMIC_SDA, E16 PE9, E17 PE10, F1 PZ0, F2 PZ1, F3 PZ2, F18 PF6, G16 PF7, G17 PF8, G18 PF9, H16 PF10, H17 PG7, M17 PG9, N3 PI7, P1 PI4, P2 PI5, P3 PI6, R1 PI1, R2 PI2, R3 PI3, R17 PE4, T1 PH14, T2 PH15, T3 PI0, T4 PH8, T5 PE13, T6 PH5, T7 PE1, T8 PF5, T9 PE6, T12 PE3, T18 PF2, U1 PH13, U2 PH12, U3 PH10, U4 PE15, U5 PE12, U6 PH4, U7 PE0, U8 PF0, U15 PG6, V2 PH11, V3 PH9, V4 PE14, V5 PE11, V7 PF4, V8 PF1, V9 PG15, V15 PE5
part D pins: J17 USB_DM2, J18 USB_DP2, K1 VSSA, K2 VREF-, K9 OTG_VBUS, K17 USB_DP1, K18 USB_DM1, L1 ANA0, L2 ANA1, M1 VDDA, M2 VREF+, N16 DSI_CK_P, N17 DSI_D1_P, N18 DSI_D1_N, P16 DSI_CK_N, P17 DSI_D0_P, P18 DSI_D0_N, R11 NJTRST, R12 JTDO-TRACESWO, R13 JTDI, R14 JTMS-SWDIO, R15 JTCK-SWCLK
part E pins: D4 VSS, E4 VSS, E5 VSS, E6 VSS, E7 VSS, E8 VSS, E9 VSS, E10 VSS, E11 VSS, E12 VSS, E13 VSS, E14 VSS, E15 VSS, F4 VSS, F5 VSS, F6 VSS, F7 VSS, F8 VSS, F9 VSS, F10 VSS, F11 VSS, F12 VSS, F13 VSS, F14 VSS, F15 VSS, G5 VSS, G11 VSS, G12 VSS, G13 VSS, G14 VSS, G15 VSS, H5 VSS, H13 VSS, H14 VSS, H15 VSS, J5 VSS, J13 VSS, J14 VSS, J15 VSS, J16 VSS, K5 VSS, K13 VSS, K14 VSS, K15 VSS, K16 VSS, L5 VSS, L13 VSS, L14 VSS, L15 VSS, M5 VSS, M11 VSS, M12 VSS, M13 VSS, M14 VSS, M15 VSS, N5 VSS, N6 VSS, N7 VSS, N8 VSS, N9 VSS, N10 VSS, N11 VSS, N12 VSS, N13 VSS, N14 VSS, N15 VSS, P5 VSS, P6 VSS, P7 VSS, P8 VSS
part F pins: D5 PWR_ON/PMIC_PWRCTRL, D6 PC13/PMIC_WAKEUP, J2 HSE_OSC_TP, J12 VTT_DDR, K6 PWR_LP, K12 VDD_DDR, L3 PA0/PMIC_INTN, L6 PDR_ON_CORE, L12 VREF_DDR, M6 PDR_ON, N4 NRST_CORE, R4 VDD_CORE, R5 VDD3V3_USB, R6 VDD1V2_DSI_REG, R7 VDDA1V8_REG, R8 VDDA1V1_REG
part G pins: D7 RSVD, D8 RSVD, D9 RSVD, D10 RSVD, H12 RSVD, M16 RSVD, P9 RSVD, P10 RSVD, R9 RSVD, R10 RSVD

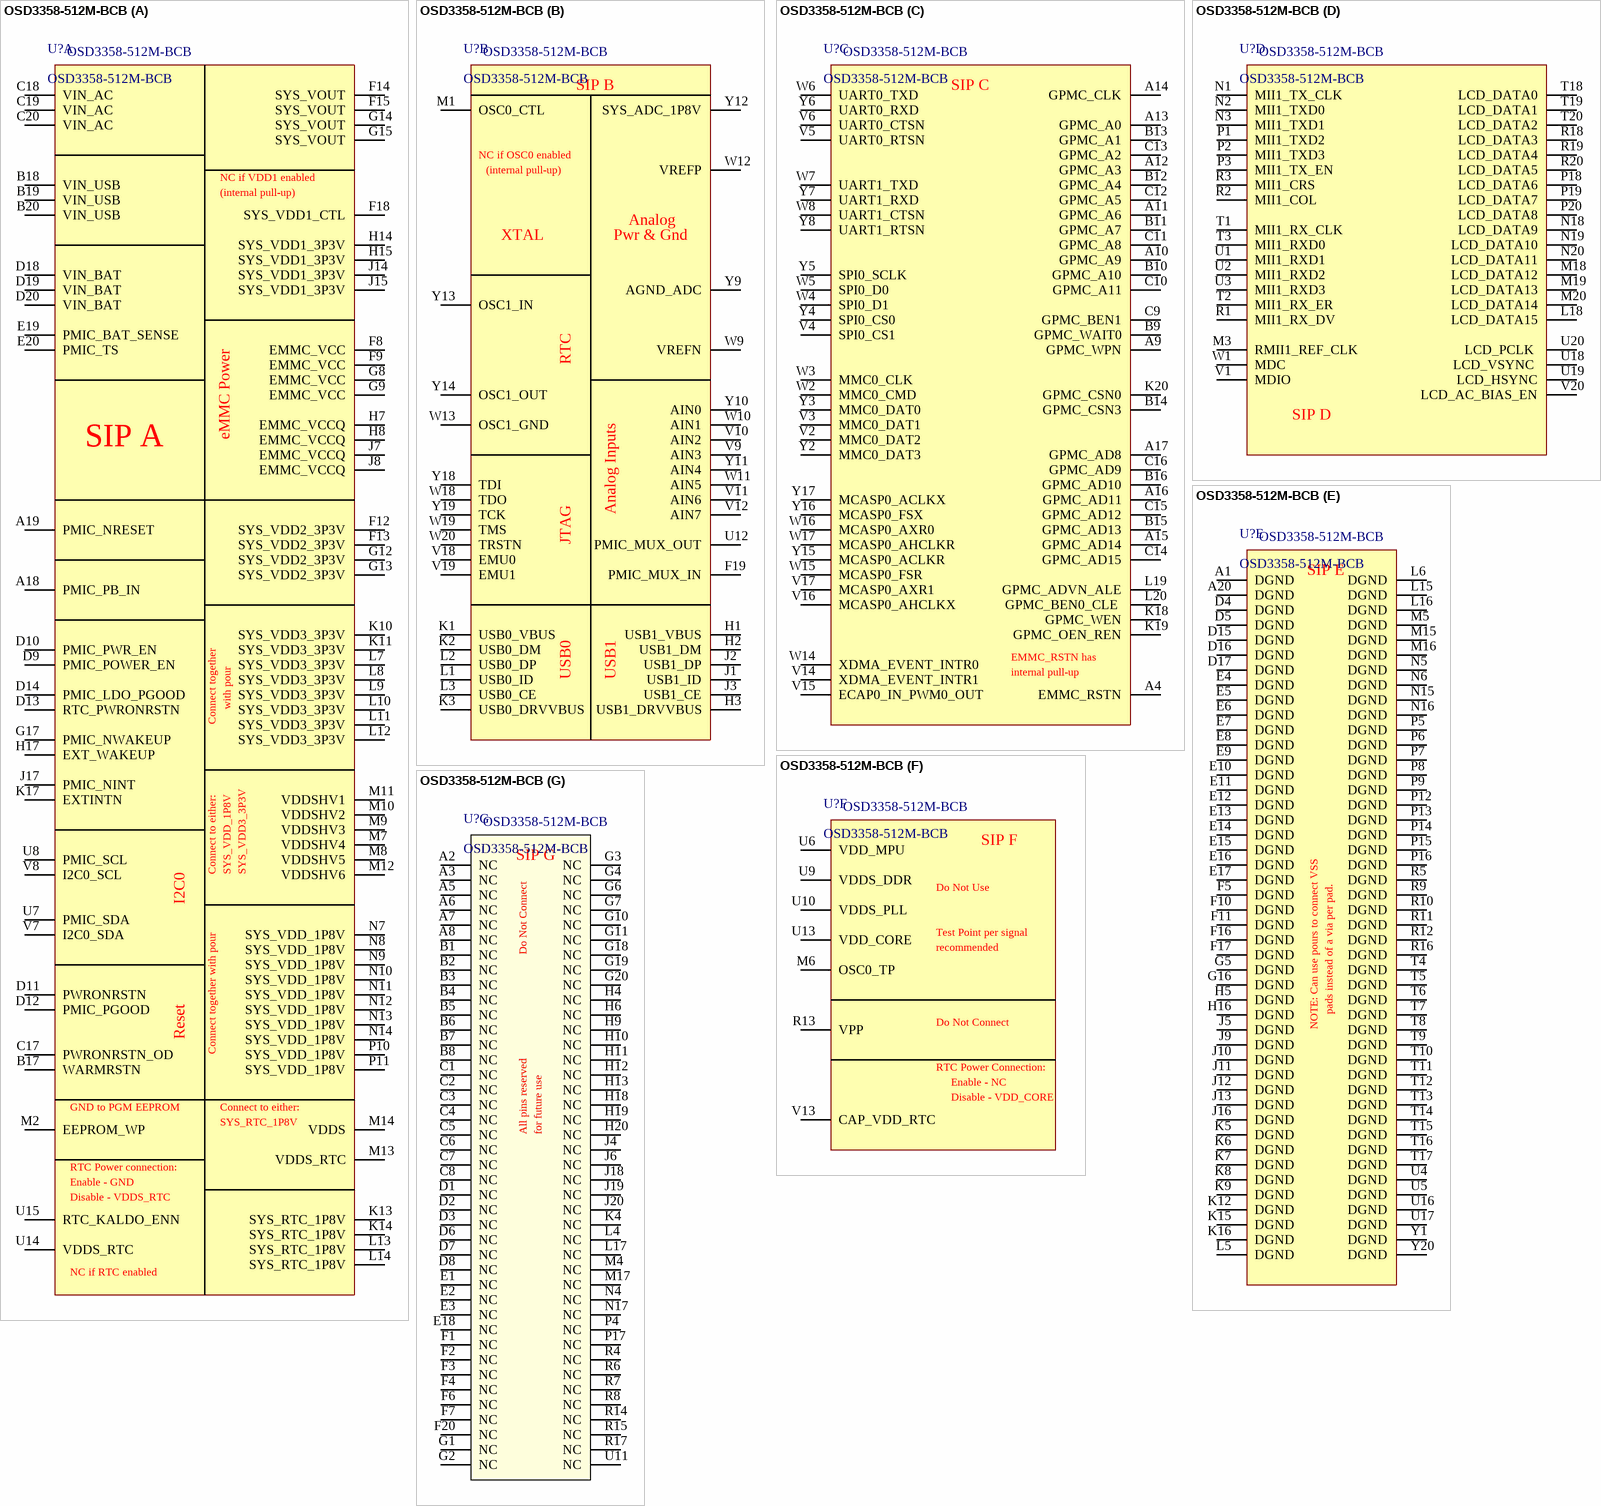
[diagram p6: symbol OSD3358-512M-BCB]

## OSD3358-512M-BCB
designator U?
Octavo Systems OSD335x Family SiP:  27mm x 27mm, 1.27mm pitch 400 pin BGA contains AM3358, 512MB DDR3, TPS65217C, TL5209, 4KB EEPROM, 4GB eMMC, 24MHz oscillator, and passives.  Commercial Temperature (case):  0C to 85C.
footprint BGA_20x20_400_1p27mm (400 pin 1.27mm pitch footprint)
part A pins: A18 PMIC_PB_IN, A19 PMIC_NRESET, B17 WARMRSTN, B18 VIN_USB (power), B19 VIN_USB (power), B20 VIN_USB (power), C17 PWRONRSTN_OD, C18 VIN_AC (power), C19 VIN_AC (power), C20 VIN_AC (power), D9 PMIC_POWER_EN, D10 PMIC_PWR_EN, D11 PWRONRSTN, D12 PMIC_PGOOD, D13 RTC_PWRONRSTN, D14 PMIC_LDO_PGOOD, D18 VIN_BAT (power), D19 VIN_BAT (power), D20 VIN_BAT (power), E19 PMIC_BAT_SENSE, E20 PMIC_TS, F8 EMMC_VCC (power), F9 EMMC_VCC (power), F12 SYS_VDD2_3P3V (power), F13 SYS_VDD2_3P3V (power), F14 SYS_VOUT (power), F15 SYS_VOUT (power), F18 SYS_VDD1_CTL, G8 EMMC_VCC (power), G9 EMMC_VCC (power), G12 SYS_VDD2_3P3V (power), G13 SYS_VDD2_3P3V (power), G14 SYS_VOUT (power), G15 SYS_VOUT (power), G17 PMIC_NWAKEUP, H7 EMMC_VCCQ (power), H8 EMMC_VCCQ (power), H14 SYS_VDD1_3P3V (power), H15 SYS_VDD1_3P3V (power), H17 EXT_WAKEUP, J7 EMMC_VCCQ (power), J8 EMMC_VCCQ (power), J14 SYS_VDD1_3P3V (power), J15 SYS_VDD1_3P3V (power), J17 PMIC_NINT, K10 SYS_VDD3_3P3V (power), K11 SYS_VDD3_3P3V (power), K13 SYS_RTC_1P8V (power), K14 SYS_RTC_1P8V (power), K17 EXTINTN, L7 SYS_VDD3_3P3V (power), L8 SYS_VDD3_3P3V (power), L9 SYS_VDD3_3P3V (power), L10 SYS_VDD3_3P3V (power), L11 SYS_VDD3_3P3V (power), L12 SYS_VDD3_3P3V (power), L13 SYS_RTC_1P8V (power), L14 SYS_RTC_1P8V (power), M2 EEPROM_WP, M7 VDDSHV4 (power), M8 VDDSHV5 (power), M9 VDDSHV3 (power), M10 VDDSHV2 (power), M11 VDDSHV1 (power), M12 VDDSHV6 (power), M13 VDDS_RTC (power), M14 VDDS (power), N7 SYS_VDD_1P8V (power), N8 SYS_VDD_1P8V (power), N9 SYS_VDD_1P8V (power), N10 SYS_VDD_1P8V (power), N11 SYS_VDD_1P8V (power), N12 SYS_VDD_1P8V (power), N13 SYS_VDD_1P8V (power), N14 SYS_VDD_1P8V (power), P10 SYS_VDD_1P8V (power), P11 SYS_VDD_1P8V (power), U7 PMIC_SDA, U8 PMIC_SCL, U14 VDDS_RTC (power), U15 RTC_KALDO_ENN, V7 I2C0_SDA, V8 I2C0_SCL
part B pins: F19 PMIC_MUX_IN, H1 USB1_VBUS, H2 USB1_DM, H3 USB1_DRVVBUS, J1 USB1_ID, J2 USB1_DP, J3 USB1_CE, K1 USB0_VBUS, K2 USB0_DM, K3 USB0_DRVVBUS, L1 USB0_ID, L2 USB0_DP, L3 USB0_CE, M1 OSC0_CTL, U12 PMIC_MUX_OUT, V9 AIN3, V10 AIN2, V11 AIN6, V12 AIN7, V18 EMU0, V19 EMU1, W9 VREFN (power), W10 AIN1, W11 AIN5, W12 VREFP (power), W13 OSC1_GND (power), W18 TDO, W19 TMS, W20 TRSTN, Y9 AGND_ADC (power), Y10 AIN0, Y11 AIN4, Y12 SYS_ADC_1P8V (power), Y13 OSC1_IN, Y14 OSC1_OUT, Y18 TDI, Y19 TCK
part C pins: A4 EMMC_RSTN, A9 GPMC_WPN, A10 GPMC_A9, A11 GPMC_A6, A12 GPMC_A3, A13 GPMC_A0, A14 GPMC_CLK, A15 GPMC_AD14, A16 GPMC_AD11, A17 GPMC_AD8, B9 GPMC_WAIT0, B10 GPMC_A10, B11 GPMC_A7, B12 GPMC_A4, B13 GPMC_A1, B14 GPMC_CSN3, B15 GPMC_AD13, B16 GPMC_AD10, C9 GPMC_BEN1, C10 GPMC_A11, C11 GPMC_A8, C12 GPMC_A5, C13 GPMC_A2, C14 GPMC_AD15, C15 GPMC_AD12, C16 GPMC_AD9, K18 GPMC_WEN, K19 GPMC_OEN_REN, K20 GPMC_CSN0, L19 GPMC_ADVN_ALE, L20 GPMC_BEN0_CLE , V2 MMC0_DAT2, V3 MMC0_DAT1, V4 SPI0_CS1, V5 UART0_RTSN, V6 UART0_CTSN, V14 XDMA_EVENT_INTR1, V15 ECAP0_IN_PWM0_OUT, V16 MCASP0_AHCLKX, V17 MCASP0_AXR1, W2 MMC0_CMD, W3 MMC0_CLK, W4 SPI0_D1, W5 SPI0_D0, W6 UART0_TXD, W7 UART1_TXD, W8 UART1_CTSN, W14 XDMA_EVENT_INTR0, W15 MCASP0_FSR, W16 MCASP0_AXR0, W17 MCASP0_AHCLKR, Y2 MMC0_DAT3, Y3 MMC0_DAT0, Y4 SPI0_CS0, Y5 SPI0_SCLK, Y6 UART0_RXD, Y7 UART1_RXD, Y8 UART1_RTSN, Y15 MCASP0_ACLKR, Y16 MCASP0_FSX, Y17 MCASP0_ACLKX
part D pins: L18 LCD_DATA15, M3 RMII1_REF_CLK, M18 LCD_DATA12, M19 LCD_DATA13, M20 LCD_DATA14, N1 MII1_TX_CLK, N2 MII1_TXD0, N3 MII1_TXD1, N18 LCD_DATA9, N19 LCD_DATA10, N20 LCD_DATA11, P1 MII1_TXD2, P2 MII1_TXD3, P3 MII1_TX_EN, P18 LCD_DATA6, P19 LCD_DATA7, P20 LCD_DATA8, R1 MII1_RX_DV, R2 MII1_COL, R3 MII1_CRS, R18 LCD_DATA3, R19 LCD_DATA4, R20 LCD_DATA5, T1 MII1_RX_CLK, T2 MII1_RX_ER, T3 MII1_RXD0, T18 LCD_DATA0, T19 LCD_DATA1, T20 LCD_DATA2, U1 MII1_RXD1, U2 MII1_RXD2, U3 MII1_RXD3, U18 LCD_VSYNC , U19 LCD_HSYNC, U20 LCD_PCLK , V1 MDIO, V20 LCD_AC_BIAS_EN, W1 MDC
part E pins: A1 DGND (power), A20 DGND (power), D4 DGND (power), D5 DGND (power), D15 DGND (power), D16 DGND (power), D17 DGND (power), E4 DGND (power), E5 DGND (power), E6 DGND (power), E7 DGND (power), E8 DGND (power), E9 DGND (power), E10 DGND (power), E11 DGND (power), E12 DGND (power), E13 DGND (power), E14 DGND (power), E15 DGND (power), E16 DGND (power), E17 DGND (power), F5 DGND (power), F10 DGND (power), F11 DGND (power), F16 DGND (power), F17 DGND (power), G5 DGND (power), G16 DGND (power), H5 DGND (power), H16 DGND (power), J5 DGND (power), J9 DGND (power), J10 DGND (power), J11 DGND (power), J12 DGND (power), J13 DGND (power), J16 DGND (power), K5 DGND (power), K6 DGND (power), K7 DGND (power), K8 DGND (power), K9 DGND (power), K12 DGND (power), K15 DGND (power), K16 DGND (power), L5 DGND (power), L6 DGND (power), L15 DGND (power), L16 DGND (power), M5 DGND (power), M15 DGND (power), M16 DGND (power), N5 DGND (power), N6 DGND (power), N15 DGND (power), N16 DGND (power), P5 DGND (power), P6 DGND (power), P7 DGND (power), P8 DGND (power), P9 DGND (power), P12 DGND (power), P13 DGND (power), P14 DGND (power), P15 DGND (power), P16 DGND (power), R5 DGND (power), R9 DGND (power), R10 DGND (power), R11 DGND (power), R12 DGND (power), R16 DGND (power), T4 DGND (power), T5 DGND (power), T6 DGND (power), T7 DGND (power), T8 DGND (power), T9 DGND (power), T10 DGND (power), T11 DGND (power), T12 DGND (power), T13 DGND (power), T14 DGND (power), T15 DGND (power), T16 DGND (power), T17 DGND (power), U4 DGND (power), U5 DGND (power), U16 DGND (power), U17 DGND (power) "U17", Y1 DGND (power), Y20 DGND (power)
part F pins: M6 OSC0_TP, R13 VPP (power), U6 VDD_MPU (power), U9 VDDS_DDR (power), U10 VDDS_PLL (power), U13 VDD_CORE (power), V13 CAP_VDD_RTC (power)
part G pins: A2 NC, A3 NC, A5 NC, A6 NC, A7 NC, A8 NC, B1 NC, B2 NC, B3 NC, B4 NC, B5 NC, B6 NC, B7 NC, B8 NC, C1 NC, C2 NC, C3 NC, C4 NC, C5 NC, C6 NC, C7 NC, C8 NC, D1 NC, D2 NC, D3 NC, D6 NC, D7 NC, D8 NC, E1 NC, E2 NC, E3 NC, E18 NC, F1 NC, F2 NC, F3 NC, F4 NC, F6 NC (power), F7 NC (power), F20 NC, G1 NC, G2 NC, G3 NC, G4 NC, G6 NC (power), G7 NC (power), G10 NC, G11 NC, G18 NC, G19 NC, G20 NC, H4 NC, H6 NC, H9 NC, H10 NC, H11 NC, H12 NC, H13 NC, H18 NC, H19 NC, H20 NC, J4 NC, J6 NC, J18 NC, J19 NC, J20 NC, K4 NC, L4 NC, L17 NC, M4 NC, M17 NC, N4 NC, N17 NC, P4 NC, P17 NC, R4 NC, R6 NC, R7 NC, R8 NC (power), R14 NC, R15 NC, R17 NC, U11 NC

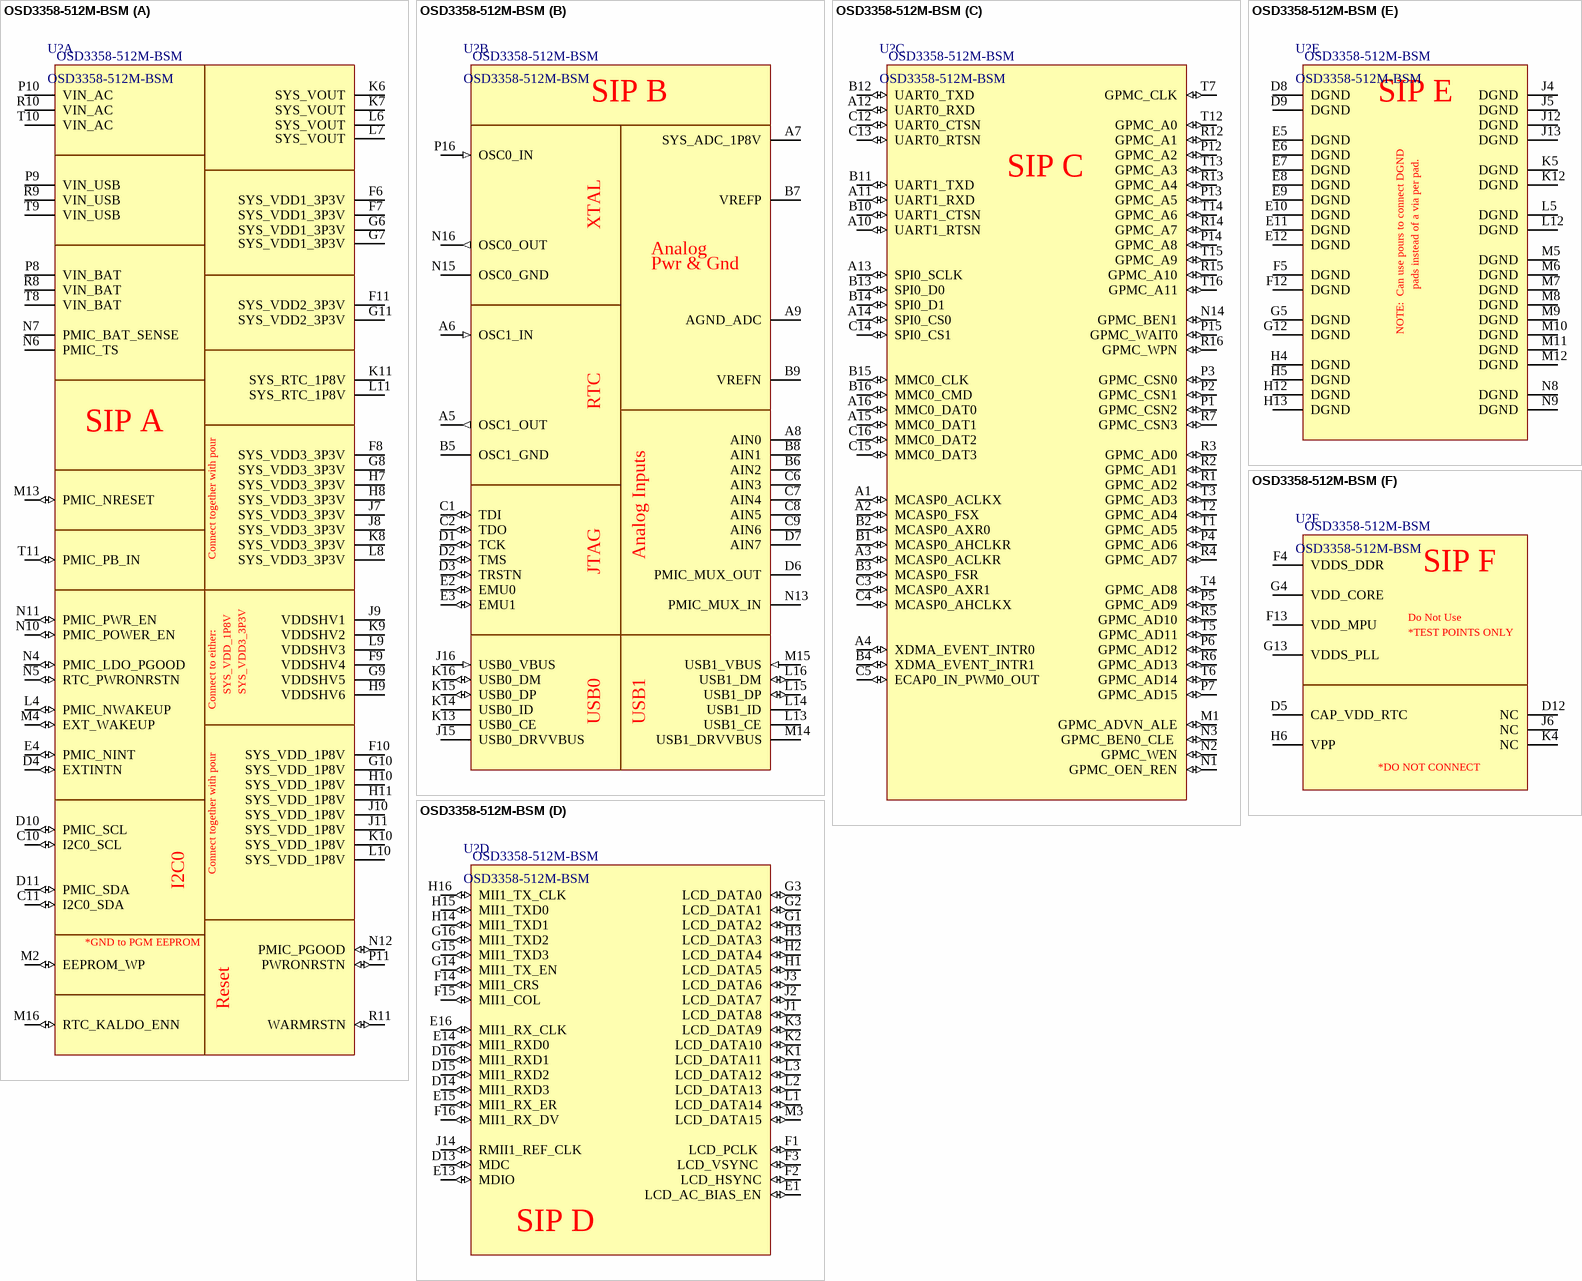
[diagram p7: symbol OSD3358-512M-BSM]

## OSD3358-512M-BSM
designator U?
Octavo Systems LLC OSD335x Family SiP:  21mm x 21mm, 1.27mm pitch 256 pin BGA contains AM3358, 512MB DDR3L, TPS65217C, TL5209, 4KB EEPROM, and passives.  Commerical Temperature (case):  0C to 85C.
footprint BGA_16x16_256_1p27mm (256 pin 1.27mm pitch footprint)
part A pins: C10 I2C0_SCL (io), C11 I2C0_SDA (io), D4 EXTINTN (io), D10 PMIC_SCL (io), D11 PMIC_SDA (io), E4 PMIC_NINT (io), F6 SYS_VDD1_3P3V (power), F7 SYS_VDD1_3P3V (power), F8 SYS_VDD3_3P3V (power), F9 VDDSHV4 (power), F10 SYS_VDD_1P8V (power), F11 SYS_VDD2_3P3V (power), G6 SYS_VDD1_3P3V (power), G7 SYS_VDD1_3P3V (power), G8 SYS_VDD3_3P3V (power), G9 VDDSHV5 (power), G10 SYS_VDD_1P8V (power), G11 SYS_VDD2_3P3V (power), H7 SYS_VDD3_3P3V (power), H8 SYS_VDD3_3P3V (power), H9 VDDSHV6 (power), H10 SYS_VDD_1P8V (power), H11 SYS_VDD_1P8V (power), J7 SYS_VDD3_3P3V (power), J8 SYS_VDD3_3P3V (power), J9 VDDSHV1 (power), J10 SYS_VDD_1P8V (power), J11 SYS_VDD_1P8V (power), K6 SYS_VOUT (power), K7 SYS_VOUT (power), K8 SYS_VDD3_3P3V (power), K9 VDDSHV2 (power), K10 SYS_VDD_1P8V (power), K11 SYS_RTC_1P8V (power), L4 PMIC_NWAKEUP (io), L6 SYS_VOUT (power), L7 SYS_VOUT (power), L8 SYS_VDD3_3P3V (power), L9 VDDSHV3 (power), L10 SYS_VDD_1P8V (power), L11 SYS_RTC_1P8V (power), M2 EEPROM_WP (io), M4 EXT_WAKEUP (io), M13 PMIC_NRESET (io), M16 RTC_KALDO_ENN (io), N4 PMIC_LDO_PGOOD (io), N5 RTC_PWRONRSTN (io), N6 PMIC_TS, N7 PMIC_BAT_SENSE, N10 PMIC_POWER_EN (io), N11 PMIC_PWR_EN (io), N12 PMIC_PGOOD (io), P8 VIN_BAT (power), P9 VIN_USB (power), P10 VIN_AC (power), P11 PWRONRSTN (io), R8 VIN_BAT (power), R9 VIN_USB (power), R10 VIN_AC (power), R11 WARMRSTN (io), T8 VIN_BAT (power), T9 VIN_USB (power), T10 VIN_AC (power), T11 PMIC_PB_IN (io)
part B pins: A5 OSC1_OUT (out), A6 OSC1_IN (in), A7 SYS_ADC_1P8V (power), A8 AIN0, A9 AGND_ADC (power), B5 OSC1_GND (power), B6 AIN2, B7 VREFP (power), B8 AIN1, B9 VREFN (power), C1 TDI (io), C2 TDO (io), C6 AIN3, C7 AIN4, C8 AIN5, C9 AIN6, D1 TCK (io), D2 TMS (io), D3 TRSTN (io), D6 PMIC_MUX_OUT, D7 AIN7, E2 EMU0 (io), E3 EMU1 (io), J15 USB0_DRVVBUS (power), J16 USB0_VBUS (in), K13 USB0_CE (power), K14 USB0_ID, K15 USB0_DP (io), K16 USB0_DM (io), L13 USB1_CE (power), L14 USB1_ID, L15 USB1_DP (io), L16 USB1_DM (io), M14 USB1_DRVVBUS (power), M15 USB1_VBUS (in), N13 PMIC_MUX_IN, N15 OSC0_GND (power), N16 OSC0_OUT (out), P16 OSC0_IN (in)
part C pins: A1 MCASP0_ACLKX (io), A2 MCASP0_FSX (io), A3 MCASP0_ACLKR (io), A4 XDMA_EVENT_INTR0 (io), A10 UART1_RTSN (io), A11 UART1_RXD (io), A12 UART0_RXD (io), A13 SPI0_SCLK (io), A14 SPI0_CS0 (io), A15 MMC0_DAT1 (io), A16 MMC0_DAT0 (io), B1 MCASP0_AHCLKR (io), B2 MCASP0_AXR0 (io), B3 MCASP0_FSR (io), B4 XDMA_EVENT_INTR1 (io), B10 UART1_CTSN (io), B11 UART1_TXD (io), B12 UART0_TXD (io), B13 SPI0_D0 (io), B14 SPI0_D1 (io), B15 MMC0_CLK (io), B16 MMC0_CMD (io), C3 MCASP0_AXR1 (io), C4 MCASP0_AHCLKX (io), C5 ECAP0_IN_PWM0_OUT (io), C12 UART0_CTSN (io), C13 UART0_RTSN (io), C14 SPI0_CS1 (io), C15 MMC0_DAT3 (io), C16 MMC0_DAT2 (io), M1 GPMC_ADVN_ALE (io), N1 GPMC_OEN_REN (io), N2 GPMC_WEN (io), N3 GPMC_BEN0_CLE  (io), N14 GPMC_BEN1 (io), P1 GPMC_CSN2 (io), P2 GPMC_CSN1 (io), P3 GPMC_CSN0 (io), P4 GPMC_AD6 (io), P5 GPMC_AD9 (io), P6 GPMC_AD12 (io), P7 GPMC_AD15 (io), P12 GPMC_A2 (io), P13 GPMC_A5 (io), P14 GPMC_A8 (io), P15 GPMC_WAIT0 (io), R1 GPMC_AD2 (io), R2 GPMC_AD1 (io), R3 GPMC_AD0 (io), R4 GPMC_AD7 (io), R5 GPMC_AD10 (io), R6 GPMC_AD13 (io), R7 GPMC_CSN3 (io), R12 GPMC_A1 (io), R13 GPMC_A4 (io), R14 GPMC_A7 (io), R15 GPMC_A10 (io), R16 GPMC_WPN (io), T1 GPMC_AD5 (io), T2 GPMC_AD4 (io), T3 GPMC_AD3 (io), T4 GPMC_AD8 (io), T5 GPMC_AD11 (io), T6 GPMC_AD14 (io), T7 GPMC_CLK (io), T12 GPMC_A0 (io), T13 GPMC_A3 (io), T14 GPMC_A6 (io), T15 GPMC_A9 (io), T16 GPMC_A11 (io)
part D pins: D13 MDC (io), D14 MII1_RXD3 (io), D15 MII1_RXD2 (io), D16 MII1_RXD1 (io), E1 LCD_AC_BIAS_EN (io), E13 MDIO (io), E14 MII1_RXD0 (io), E15 MII1_RX_ER (io), E16  MII1_RX_CLK (io), F1 LCD_PCLK  (io), F2 LCD_HSYNC (io), F3 LCD_VSYNC  (io), F14 MII1_CRS (io), F15 MII1_COL (io), F16 MII1_RX_DV (io), G1 LCD_DATA2 (io), G2 LCD_DATA1 (io), G3 LCD_DATA0 (io), G14 MII1_TX_EN (io), G15 MII1_TXD3 (io), G16 MII1_TXD2 (io), H1 LCD_DATA5 (io), H2 LCD_DATA4 (io), H3 LCD_DATA3 (io), H14 MII1_TXD1 (io), H15 MII1_TXD0 (io), H16  MII1_TX_CLK (io), J1 LCD_DATA8 (io), J2 LCD_DATA7 (io), J3 LCD_DATA6 (io), J14 RMII1_REF_CLK (io), K1 LCD_DATA11 (io), K2 LCD_DATA10 (io), K3 LCD_DATA9 (io), L1 LCD_DATA14 (io), L2 LCD_DATA13 (io), L3 LCD_DATA12 (io), M3 LCD_DATA15 (io)
part E pins: D8 DGND (power), D9 DGND (power), E5 DGND (power), E6 DGND (power), E7 DGND (power), E8 DGND (power), E9 DGND (power), E10 DGND (power), E11 DGND (power), E12 DGND (power), F5 DGND (power), F12 DGND (power), G5 DGND (power), G12 DGND (power), H4 DGND (power), H5 DGND (power), H12 DGND (power), H13 DGND (power), J4 DGND (power), J5 DGND (power), J12 DGND (power), J13 DGND (power), K5 DGND (power), K12 DGND (power), L5 DGND (power), L12 DGND (power), M5 DGND (power), M6 DGND (power), M7 DGND (power), M8 DGND (power), M9 DGND (power), M10 DGND (power), M11 DGND (power), M12 DGND (power), N8 DGND (power), N9 DGND (power)
part F pins: D5 CAP_VDD_RTC (power), D12 NC (power), F4 VDDS_DDR (power), F13 VDD_MPU (power), G4 VDD_CORE (power), G13 VDDS_PLL (power), H6 VPP (power), J6 NC (power), K4 NC (power)

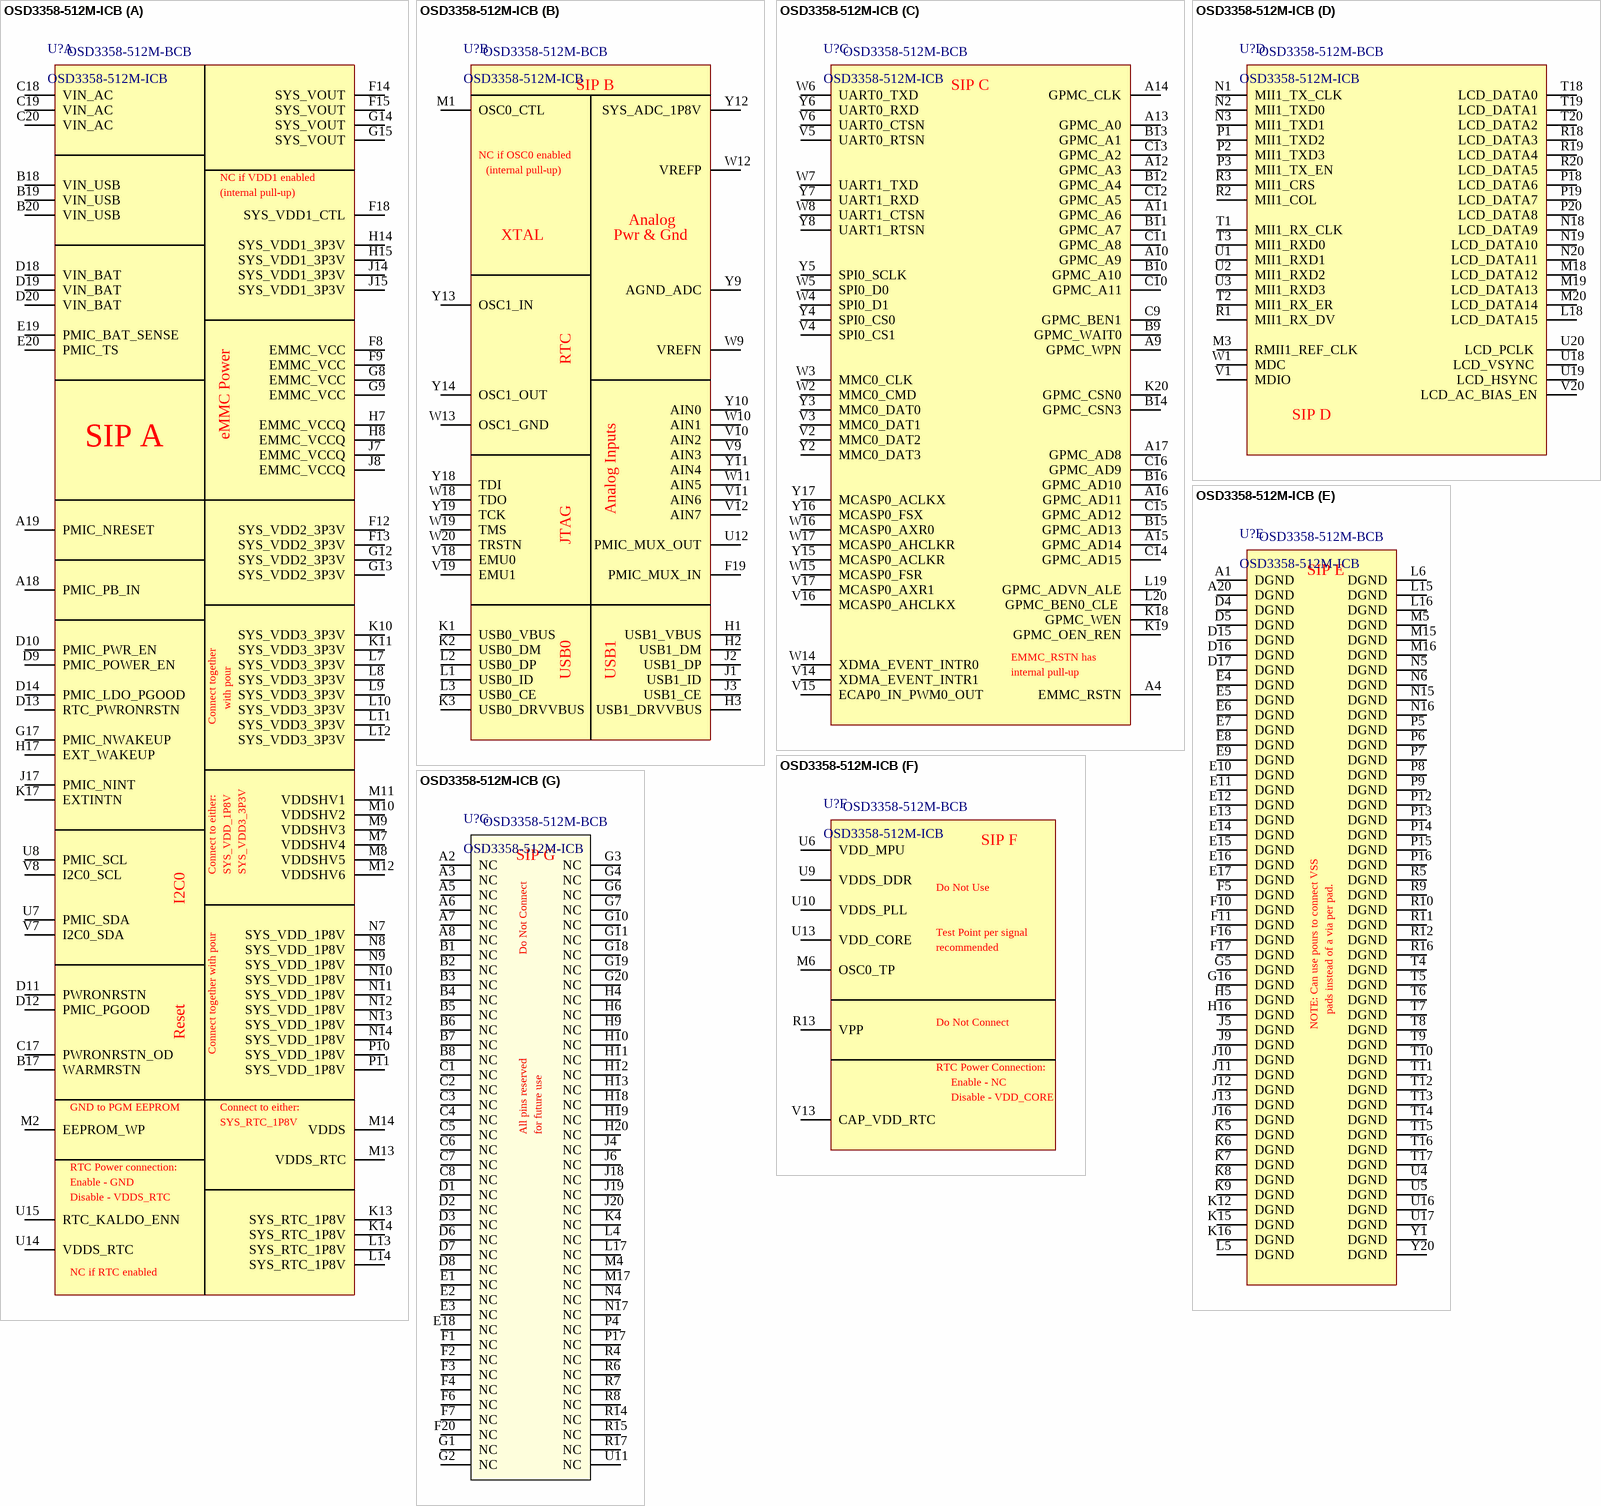
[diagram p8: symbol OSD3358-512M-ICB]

## OSD3358-512M-ICB
designator U?  PartNumber: OSD3358-512M-BCB
Octavo Systems OSD335x Family SiP:  27mm x 27mm, 1.27mm pitch 400 pin BGA contains AM3358, 512MB DDR3, TPS65217C, TL5209, 4KB EEPROM, 4GB eMMC, 24MHz oscillator, and passives.  Industrial Temperature (case):  -40C to 85C.
footprint BGA_20x20_400_1p27mm (400 pin 1.27mm pitch footprint)
part A pins: A18 PMIC_PB_IN, A19 PMIC_NRESET, B17 WARMRSTN, B18 VIN_USB (power), B19 VIN_USB (power), B20 VIN_USB (power), C17 PWRONRSTN_OD, C18 VIN_AC (power), C19 VIN_AC (power), C20 VIN_AC (power), D9 PMIC_POWER_EN, D10 PMIC_PWR_EN, D11 PWRONRSTN, D12 PMIC_PGOOD, D13 RTC_PWRONRSTN, D14 PMIC_LDO_PGOOD, D18 VIN_BAT (power), D19 VIN_BAT (power), D20 VIN_BAT (power), E19 PMIC_BAT_SENSE, E20 PMIC_TS, F8 EMMC_VCC (power), F9 EMMC_VCC (power), F12 SYS_VDD2_3P3V (power), F13 SYS_VDD2_3P3V (power), F14 SYS_VOUT (power), F15 SYS_VOUT (power), F18 SYS_VDD1_CTL, G8 EMMC_VCC (power), G9 EMMC_VCC (power), G12 SYS_VDD2_3P3V (power), G13 SYS_VDD2_3P3V (power), G14 SYS_VOUT (power), G15 SYS_VOUT (power), G17 PMIC_NWAKEUP, H7 EMMC_VCCQ (power), H8 EMMC_VCCQ (power), H14 SYS_VDD1_3P3V (power), H15 SYS_VDD1_3P3V (power), H17 EXT_WAKEUP, J7 EMMC_VCCQ (power), J8 EMMC_VCCQ (power), J14 SYS_VDD1_3P3V (power), J15 SYS_VDD1_3P3V (power), J17 PMIC_NINT, K10 SYS_VDD3_3P3V (power), K11 SYS_VDD3_3P3V (power), K13 SYS_RTC_1P8V (power), K14 SYS_RTC_1P8V (power), K17 EXTINTN, L7 SYS_VDD3_3P3V (power), L8 SYS_VDD3_3P3V (power), L9 SYS_VDD3_3P3V (power), L10 SYS_VDD3_3P3V (power), L11 SYS_VDD3_3P3V (power), L12 SYS_VDD3_3P3V (power), L13 SYS_RTC_1P8V (power), L14 SYS_RTC_1P8V (power), M2 EEPROM_WP, M7 VDDSHV4 (power), M8 VDDSHV5 (power), M9 VDDSHV3 (power), M10 VDDSHV2 (power), M11 VDDSHV1 (power), M12 VDDSHV6 (power), M13 VDDS_RTC (power), M14 VDDS (power), N7 SYS_VDD_1P8V (power), N8 SYS_VDD_1P8V (power), N9 SYS_VDD_1P8V (power), N10 SYS_VDD_1P8V (power), N11 SYS_VDD_1P8V (power), N12 SYS_VDD_1P8V (power), N13 SYS_VDD_1P8V (power), N14 SYS_VDD_1P8V (power), P10 SYS_VDD_1P8V (power), P11 SYS_VDD_1P8V (power), U7 PMIC_SDA, U8 PMIC_SCL, U14 VDDS_RTC (power), U15 RTC_KALDO_ENN, V7 I2C0_SDA, V8 I2C0_SCL
part B pins: F19 PMIC_MUX_IN, H1 USB1_VBUS, H2 USB1_DM, H3 USB1_DRVVBUS, J1 USB1_ID, J2 USB1_DP, J3 USB1_CE, K1 USB0_VBUS, K2 USB0_DM, K3 USB0_DRVVBUS, L1 USB0_ID, L2 USB0_DP, L3 USB0_CE, M1 OSC0_CTL, U12 PMIC_MUX_OUT, V9 AIN3, V10 AIN2, V11 AIN6, V12 AIN7, V18 EMU0, V19 EMU1, W9 VREFN (power), W10 AIN1, W11 AIN5, W12 VREFP (power), W13 OSC1_GND (power), W18 TDO, W19 TMS, W20 TRSTN, Y9 AGND_ADC (power), Y10 AIN0, Y11 AIN4, Y12 SYS_ADC_1P8V (power), Y13 OSC1_IN, Y14 OSC1_OUT, Y18 TDI, Y19 TCK
part C pins: A4 EMMC_RSTN, A9 GPMC_WPN, A10 GPMC_A9, A11 GPMC_A6, A12 GPMC_A3, A13 GPMC_A0, A14 GPMC_CLK, A15 GPMC_AD14, A16 GPMC_AD11, A17 GPMC_AD8, B9 GPMC_WAIT0, B10 GPMC_A10, B11 GPMC_A7, B12 GPMC_A4, B13 GPMC_A1, B14 GPMC_CSN3, B15 GPMC_AD13, B16 GPMC_AD10, C9 GPMC_BEN1, C10 GPMC_A11, C11 GPMC_A8, C12 GPMC_A5, C13 GPMC_A2, C14 GPMC_AD15, C15 GPMC_AD12, C16 GPMC_AD9, K18 GPMC_WEN, K19 GPMC_OEN_REN, K20 GPMC_CSN0, L19 GPMC_ADVN_ALE, L20 GPMC_BEN0_CLE , V2 MMC0_DAT2, V3 MMC0_DAT1, V4 SPI0_CS1, V5 UART0_RTSN, V6 UART0_CTSN, V14 XDMA_EVENT_INTR1, V15 ECAP0_IN_PWM0_OUT, V16 MCASP0_AHCLKX, V17 MCASP0_AXR1, W2 MMC0_CMD, W3 MMC0_CLK, W4 SPI0_D1, W5 SPI0_D0, W6 UART0_TXD, W7 UART1_TXD, W8 UART1_CTSN, W14 XDMA_EVENT_INTR0, W15 MCASP0_FSR, W16 MCASP0_AXR0, W17 MCASP0_AHCLKR, Y2 MMC0_DAT3, Y3 MMC0_DAT0, Y4 SPI0_CS0, Y5 SPI0_SCLK, Y6 UART0_RXD, Y7 UART1_RXD, Y8 UART1_RTSN, Y15 MCASP0_ACLKR, Y16 MCASP0_FSX, Y17 MCASP0_ACLKX
part D pins: L18 LCD_DATA15, M3 RMII1_REF_CLK, M18 LCD_DATA12, M19 LCD_DATA13, M20 LCD_DATA14, N1 MII1_TX_CLK, N2 MII1_TXD0, N3 MII1_TXD1, N18 LCD_DATA9, N19 LCD_DATA10, N20 LCD_DATA11, P1 MII1_TXD2, P2 MII1_TXD3, P3 MII1_TX_EN, P18 LCD_DATA6, P19 LCD_DATA7, P20 LCD_DATA8, R1 MII1_RX_DV, R2 MII1_COL, R3 MII1_CRS, R18 LCD_DATA3, R19 LCD_DATA4, R20 LCD_DATA5, T1 MII1_RX_CLK, T2 MII1_RX_ER, T3 MII1_RXD0, T18 LCD_DATA0, T19 LCD_DATA1, T20 LCD_DATA2, U1 MII1_RXD1, U2 MII1_RXD2, U3 MII1_RXD3, U18 LCD_VSYNC , U19 LCD_HSYNC, U20 LCD_PCLK , V1 MDIO, V20 LCD_AC_BIAS_EN, W1 MDC
part E pins: A1 DGND (power), A20 DGND (power), D4 DGND (power), D5 DGND (power), D15 DGND (power), D16 DGND (power), D17 DGND (power), E4 DGND (power), E5 DGND (power), E6 DGND (power), E7 DGND (power), E8 DGND (power), E9 DGND (power), E10 DGND (power), E11 DGND (power), E12 DGND (power), E13 DGND (power), E14 DGND (power), E15 DGND (power), E16 DGND (power), E17 DGND (power), F5 DGND (power), F10 DGND (power), F11 DGND (power), F16 DGND (power), F17 DGND (power), G5 DGND (power), G16 DGND (power), H5 DGND (power), H16 DGND (power), J5 DGND (power), J9 DGND (power), J10 DGND (power), J11 DGND (power), J12 DGND (power), J13 DGND (power), J16 DGND (power), K5 DGND (power), K6 DGND (power), K7 DGND (power), K8 DGND (power), K9 DGND (power), K12 DGND (power), K15 DGND (power), K16 DGND (power), L5 DGND (power), L6 DGND (power), L15 DGND (power), L16 DGND (power), M5 DGND (power), M15 DGND (power), M16 DGND (power), N5 DGND (power), N6 DGND (power), N15 DGND (power), N16 DGND (power), P5 DGND (power), P6 DGND (power), P7 DGND (power), P8 DGND (power), P9 DGND (power), P12 DGND (power), P13 DGND (power), P14 DGND (power), P15 DGND (power), P16 DGND (power), R5 DGND (power), R9 DGND (power), R10 DGND (power), R11 DGND (power), R12 DGND (power), R16 DGND (power), T4 DGND (power), T5 DGND (power), T6 DGND (power), T7 DGND (power), T8 DGND (power), T9 DGND (power), T10 DGND (power), T11 DGND (power), T12 DGND (power), T13 DGND (power), T14 DGND (power), T15 DGND (power), T16 DGND (power), T17 DGND (power), U4 DGND (power), U5 DGND (power), U16 DGND (power), U17 DGND (power) "U17", Y1 DGND (power), Y20 DGND (power)
part F pins: M6 OSC0_TP, R13 VPP (power), U6 VDD_MPU (power), U9 VDDS_DDR (power), U10 VDDS_PLL (power), U13 VDD_CORE (power), V13 CAP_VDD_RTC (power)
part G pins: A2 NC, A3 NC, A5 NC, A6 NC, A7 NC, A8 NC, B1 NC, B2 NC, B3 NC, B4 NC, B5 NC, B6 NC, B7 NC, B8 NC, C1 NC, C2 NC, C3 NC, C4 NC, C5 NC, C6 NC, C7 NC, C8 NC, D1 NC, D2 NC, D3 NC, D6 NC, D7 NC, D8 NC, E1 NC, E2 NC, E3 NC, E18 NC, F1 NC, F2 NC, F3 NC, F4 NC, F6 NC (power), F7 NC (power), F20 NC, G1 NC, G2 NC, G3 NC, G4 NC, G6 NC (power), G7 NC (power), G10 NC, G11 NC, G18 NC, G19 NC, G20 NC, H4 NC, H6 NC, H9 NC, H10 NC, H11 NC, H12 NC, H13 NC, H18 NC, H19 NC, H20 NC, J4 NC, J6 NC, J18 NC, J19 NC, J20 NC, K4 NC, L4 NC, L17 NC, M4 NC, M17 NC, N4 NC, N17 NC, P4 NC, P17 NC, R4 NC, R6 NC, R7 NC, R8 NC (power), R14 NC, R15 NC, R17 NC, U11 NC

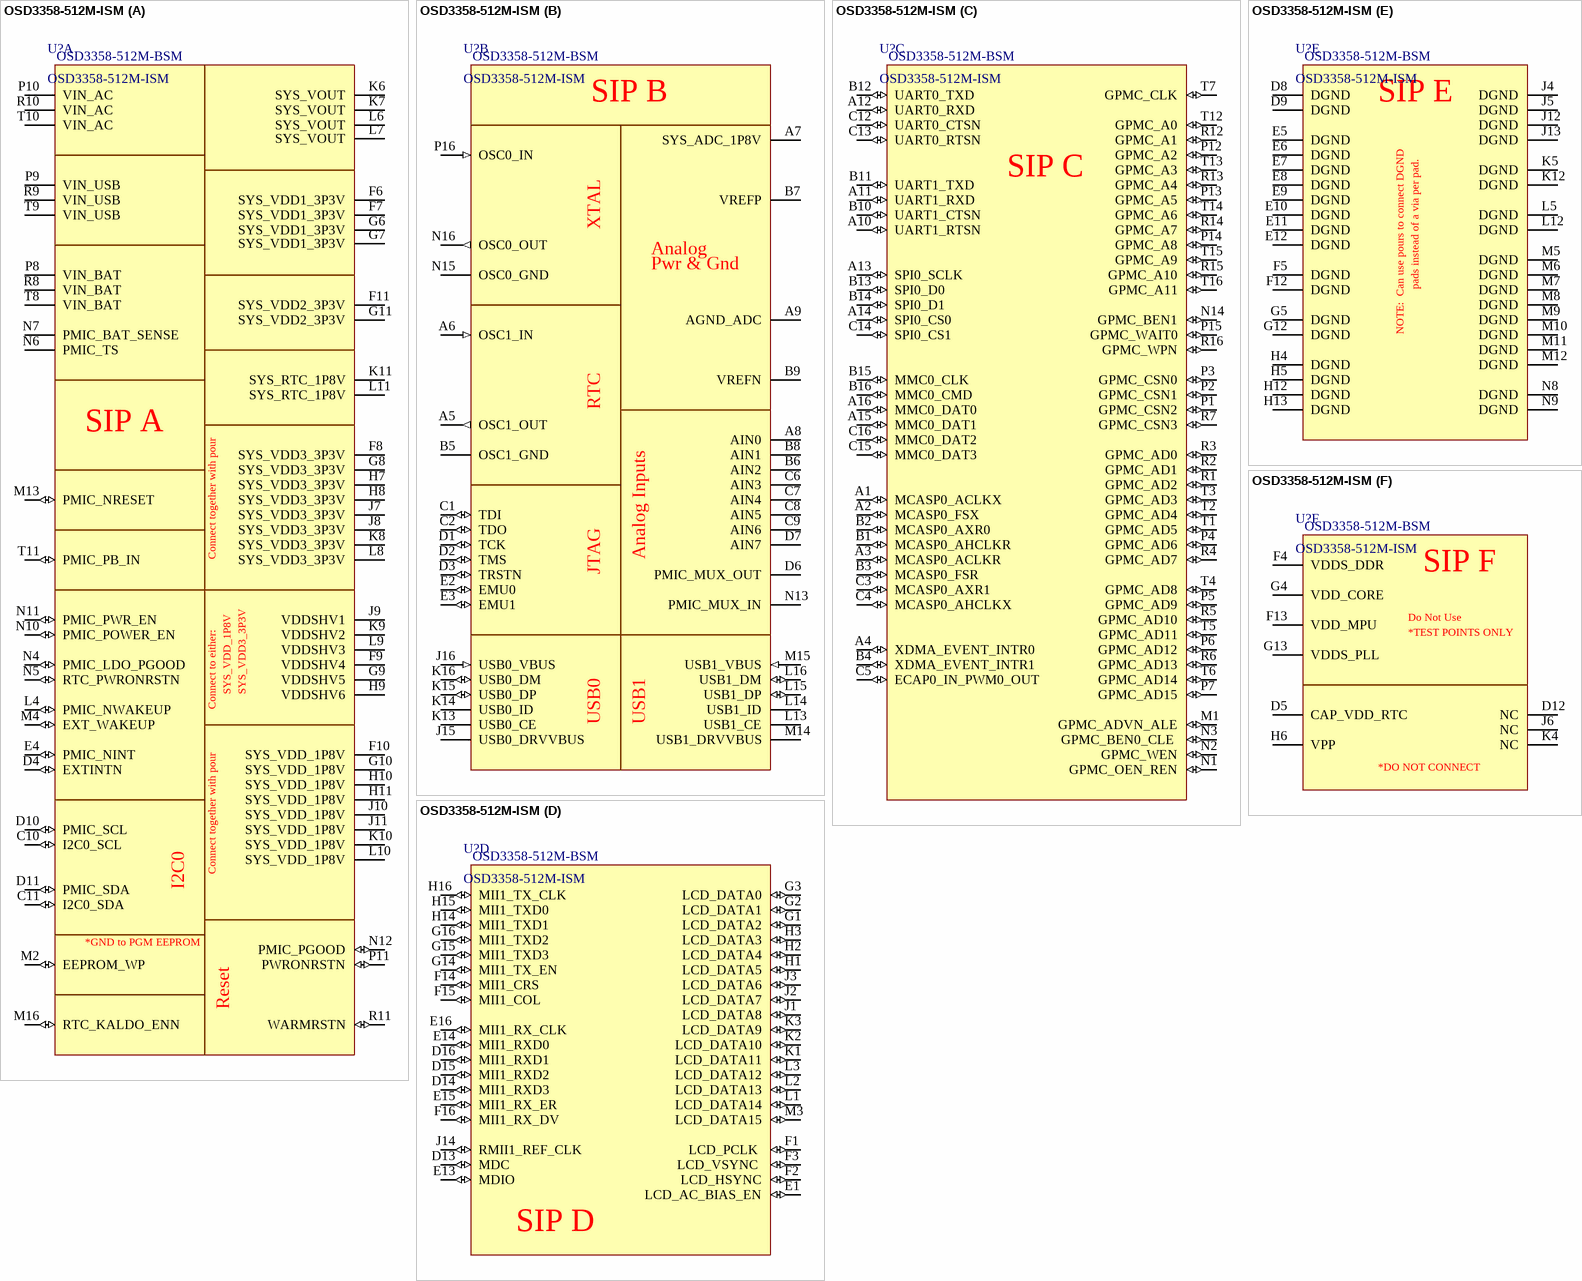
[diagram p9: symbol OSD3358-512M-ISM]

## OSD3358-512M-ISM
designator U?  PartNumber: OSD3358-512M-BSM
Octavo Systems LLC OSD335x Family SiP:  21mm x 21mm, 1.27mm pitch 256 pin BGA contains AM3358, 512MB DDR3L, TPS65217C, TL5209, 4KB EEPROM, and passives. Industrial Temperature (case):  -40C to 85C.
footprint BGA_16x16_256_1p27mm (256 pin 1.27mm pitch footprint)
part A pins: C10 I2C0_SCL (io), C11 I2C0_SDA (io), D4 EXTINTN (io), D10 PMIC_SCL (io), D11 PMIC_SDA (io), E4 PMIC_NINT (io), F6 SYS_VDD1_3P3V (power), F7 SYS_VDD1_3P3V (power), F8 SYS_VDD3_3P3V (power), F9 VDDSHV4 (power), F10 SYS_VDD_1P8V (power), F11 SYS_VDD2_3P3V (power), G6 SYS_VDD1_3P3V (power), G7 SYS_VDD1_3P3V (power), G8 SYS_VDD3_3P3V (power), G9 VDDSHV5 (power), G10 SYS_VDD_1P8V (power), G11 SYS_VDD2_3P3V (power), H7 SYS_VDD3_3P3V (power), H8 SYS_VDD3_3P3V (power), H9 VDDSHV6 (power), H10 SYS_VDD_1P8V (power), H11 SYS_VDD_1P8V (power), J7 SYS_VDD3_3P3V (power), J8 SYS_VDD3_3P3V (power), J9 VDDSHV1 (power), J10 SYS_VDD_1P8V (power), J11 SYS_VDD_1P8V (power), K6 SYS_VOUT (power), K7 SYS_VOUT (power), K8 SYS_VDD3_3P3V (power), K9 VDDSHV2 (power), K10 SYS_VDD_1P8V (power), K11 SYS_RTC_1P8V (power), L4 PMIC_NWAKEUP (io), L6 SYS_VOUT (power), L7 SYS_VOUT (power), L8 SYS_VDD3_3P3V (power), L9 VDDSHV3 (power), L10 SYS_VDD_1P8V (power), L11 SYS_RTC_1P8V (power), M2 EEPROM_WP (io), M4 EXT_WAKEUP (io), M13 PMIC_NRESET (io), M16 RTC_KALDO_ENN (io), N4 PMIC_LDO_PGOOD (io), N5 RTC_PWRONRSTN (io), N6 PMIC_TS, N7 PMIC_BAT_SENSE, N10 PMIC_POWER_EN (io), N11 PMIC_PWR_EN (io), N12 PMIC_PGOOD (io), P8 VIN_BAT (power), P9 VIN_USB (power), P10 VIN_AC (power), P11 PWRONRSTN (io), R8 VIN_BAT (power), R9 VIN_USB (power), R10 VIN_AC (power), R11 WARMRSTN (io), T8 VIN_BAT (power), T9 VIN_USB (power), T10 VIN_AC (power), T11 PMIC_PB_IN (io)
part B pins: A5 OSC1_OUT (out), A6 OSC1_IN (in), A7 SYS_ADC_1P8V (power), A8 AIN0, A9 AGND_ADC (power), B5 OSC1_GND (power), B6 AIN2, B7 VREFP (power), B8 AIN1, B9 VREFN (power), C1 TDI (io), C2 TDO (io), C6 AIN3, C7 AIN4, C8 AIN5, C9 AIN6, D1 TCK (io), D2 TMS (io), D3 TRSTN (io), D6 PMIC_MUX_OUT, D7 AIN7, E2 EMU0 (io), E3 EMU1 (io), J15 USB0_DRVVBUS (power), J16 USB0_VBUS (in), K13 USB0_CE (power), K14 USB0_ID, K15 USB0_DP (io), K16 USB0_DM (io), L13 USB1_CE (power), L14 USB1_ID, L15 USB1_DP (io), L16 USB1_DM (io), M14 USB1_DRVVBUS (power), M15 USB1_VBUS (in), N13 PMIC_MUX_IN, N15 OSC0_GND (power), N16 OSC0_OUT (out), P16 OSC0_IN (in)
part C pins: A1 MCASP0_ACLKX (io), A2 MCASP0_FSX (io), A3 MCASP0_ACLKR (io), A4 XDMA_EVENT_INTR0 (io), A10 UART1_RTSN (io), A11 UART1_RXD (io), A12 UART0_RXD (io), A13 SPI0_SCLK (io), A14 SPI0_CS0 (io), A15 MMC0_DAT1 (io), A16 MMC0_DAT0 (io), B1 MCASP0_AHCLKR (io), B2 MCASP0_AXR0 (io), B3 MCASP0_FSR (io), B4 XDMA_EVENT_INTR1 (io), B10 UART1_CTSN (io), B11 UART1_TXD (io), B12 UART0_TXD (io), B13 SPI0_D0 (io), B14 SPI0_D1 (io), B15 MMC0_CLK (io), B16 MMC0_CMD (io), C3 MCASP0_AXR1 (io), C4 MCASP0_AHCLKX (io), C5 ECAP0_IN_PWM0_OUT (io), C12 UART0_CTSN (io), C13 UART0_RTSN (io), C14 SPI0_CS1 (io), C15 MMC0_DAT3 (io), C16 MMC0_DAT2 (io), M1 GPMC_ADVN_ALE (io), N1 GPMC_OEN_REN (io), N2 GPMC_WEN (io), N3 GPMC_BEN0_CLE  (io), N14 GPMC_BEN1 (io), P1 GPMC_CSN2 (io), P2 GPMC_CSN1 (io), P3 GPMC_CSN0 (io), P4 GPMC_AD6 (io), P5 GPMC_AD9 (io), P6 GPMC_AD12 (io), P7 GPMC_AD15 (io), P12 GPMC_A2 (io), P13 GPMC_A5 (io), P14 GPMC_A8 (io), P15 GPMC_WAIT0 (io), R1 GPMC_AD2 (io), R2 GPMC_AD1 (io), R3 GPMC_AD0 (io), R4 GPMC_AD7 (io), R5 GPMC_AD10 (io), R6 GPMC_AD13 (io), R7 GPMC_CSN3 (io), R12 GPMC_A1 (io), R13 GPMC_A4 (io), R14 GPMC_A7 (io), R15 GPMC_A10 (io), R16 GPMC_WPN (io), T1 GPMC_AD5 (io), T2 GPMC_AD4 (io), T3 GPMC_AD3 (io), T4 GPMC_AD8 (io), T5 GPMC_AD11 (io), T6 GPMC_AD14 (io), T7 GPMC_CLK (io), T12 GPMC_A0 (io), T13 GPMC_A3 (io), T14 GPMC_A6 (io), T15 GPMC_A9 (io), T16 GPMC_A11 (io)
part D pins: D13 MDC (io), D14 MII1_RXD3 (io), D15 MII1_RXD2 (io), D16 MII1_RXD1 (io), E1 LCD_AC_BIAS_EN (io), E13 MDIO (io), E14 MII1_RXD0 (io), E15 MII1_RX_ER (io), E16  MII1_RX_CLK (io), F1 LCD_PCLK  (io), F2 LCD_HSYNC (io), F3 LCD_VSYNC  (io), F14 MII1_CRS (io), F15 MII1_COL (io), F16 MII1_RX_DV (io), G1 LCD_DATA2 (io), G2 LCD_DATA1 (io), G3 LCD_DATA0 (io), G14 MII1_TX_EN (io), G15 MII1_TXD3 (io), G16 MII1_TXD2 (io), H1 LCD_DATA5 (io), H2 LCD_DATA4 (io), H3 LCD_DATA3 (io), H14 MII1_TXD1 (io), H15 MII1_TXD0 (io), H16  MII1_TX_CLK (io), J1 LCD_DATA8 (io), J2 LCD_DATA7 (io), J3 LCD_DATA6 (io), J14 RMII1_REF_CLK (io), K1 LCD_DATA11 (io), K2 LCD_DATA10 (io), K3 LCD_DATA9 (io), L1 LCD_DATA14 (io), L2 LCD_DATA13 (io), L3 LCD_DATA12 (io), M3 LCD_DATA15 (io)
part E pins: D8 DGND (power), D9 DGND (power), E5 DGND (power), E6 DGND (power), E7 DGND (power), E8 DGND (power), E9 DGND (power), E10 DGND (power), E11 DGND (power), E12 DGND (power), F5 DGND (power), F12 DGND (power), G5 DGND (power), G12 DGND (power), H4 DGND (power), H5 DGND (power), H12 DGND (power), H13 DGND (power), J4 DGND (power), J5 DGND (power), J12 DGND (power), J13 DGND (power), K5 DGND (power), K12 DGND (power), L5 DGND (power), L12 DGND (power), M5 DGND (power), M6 DGND (power), M7 DGND (power), M8 DGND (power), M9 DGND (power), M10 DGND (power), M11 DGND (power), M12 DGND (power), N8 DGND (power), N9 DGND (power)
part F pins: D5 CAP_VDD_RTC (power), D12 NC (power), F4 VDDS_DDR (power), F13 VDD_MPU (power), G4 VDD_CORE (power), G13 VDDS_PLL (power), H6 VPP (power), J6 NC (power), K4 NC (power)

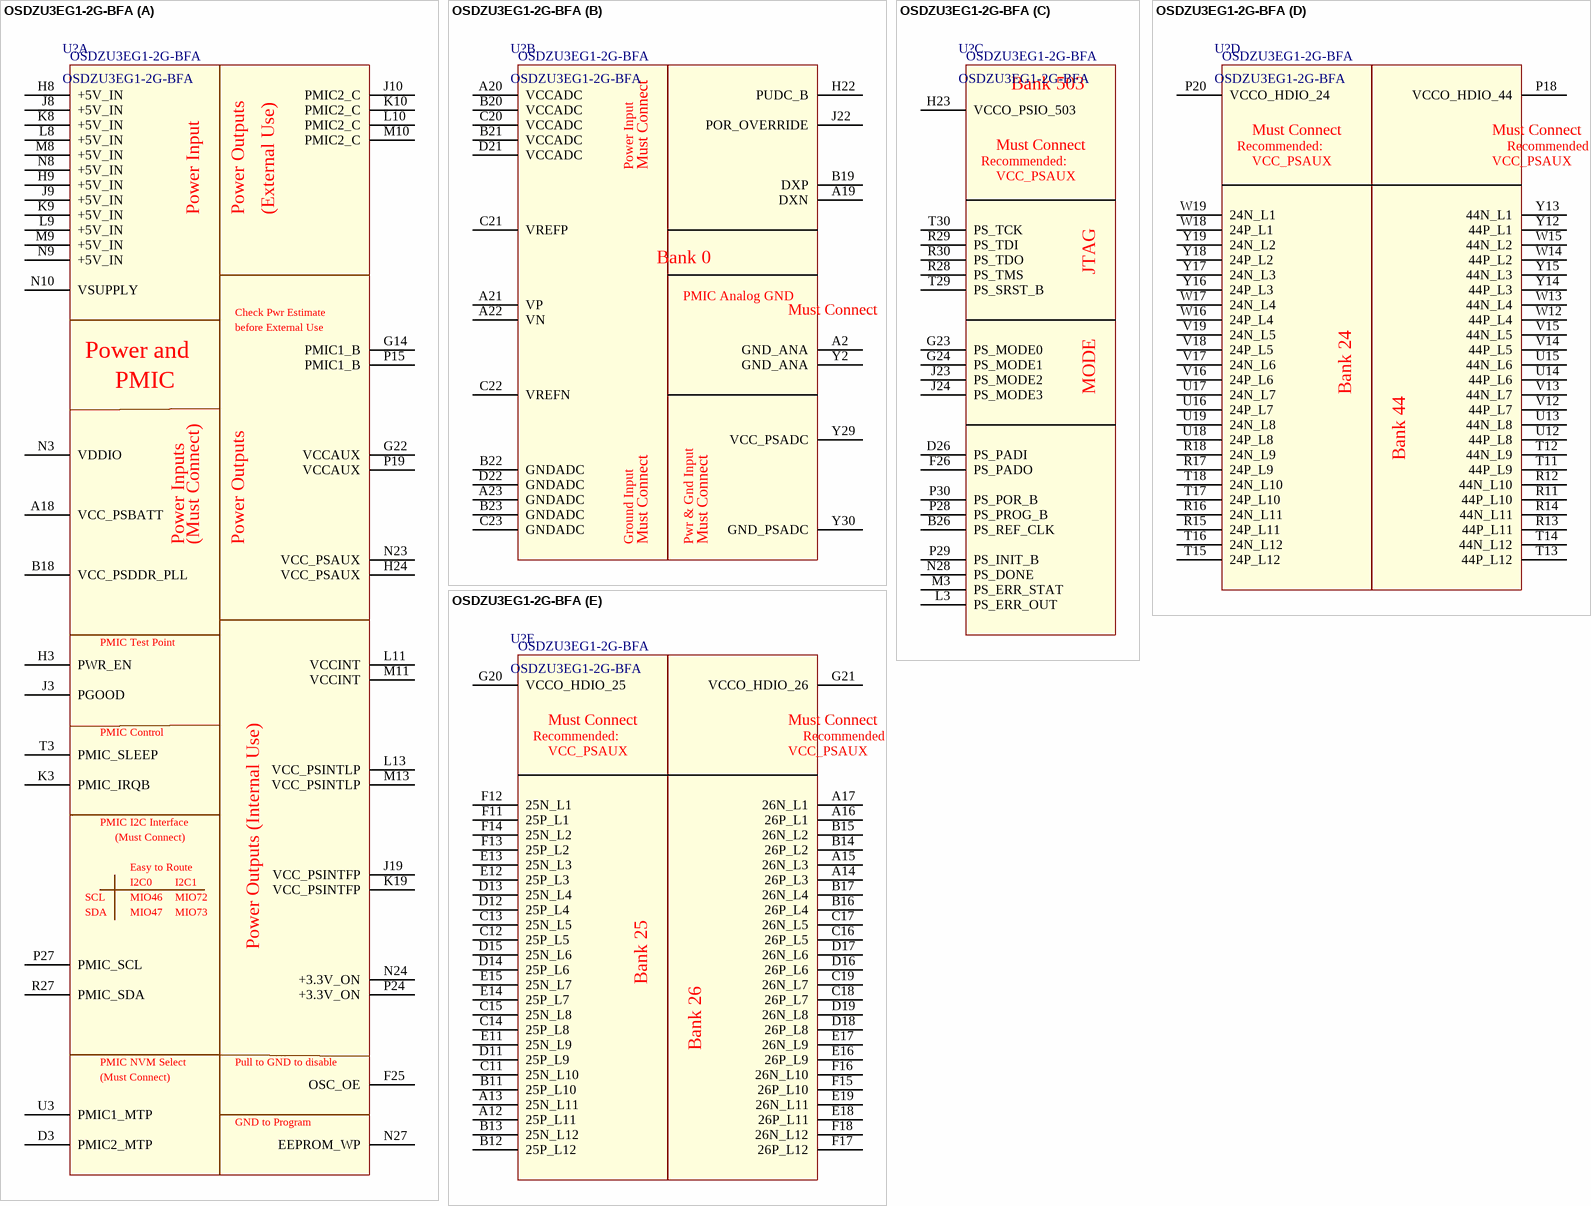
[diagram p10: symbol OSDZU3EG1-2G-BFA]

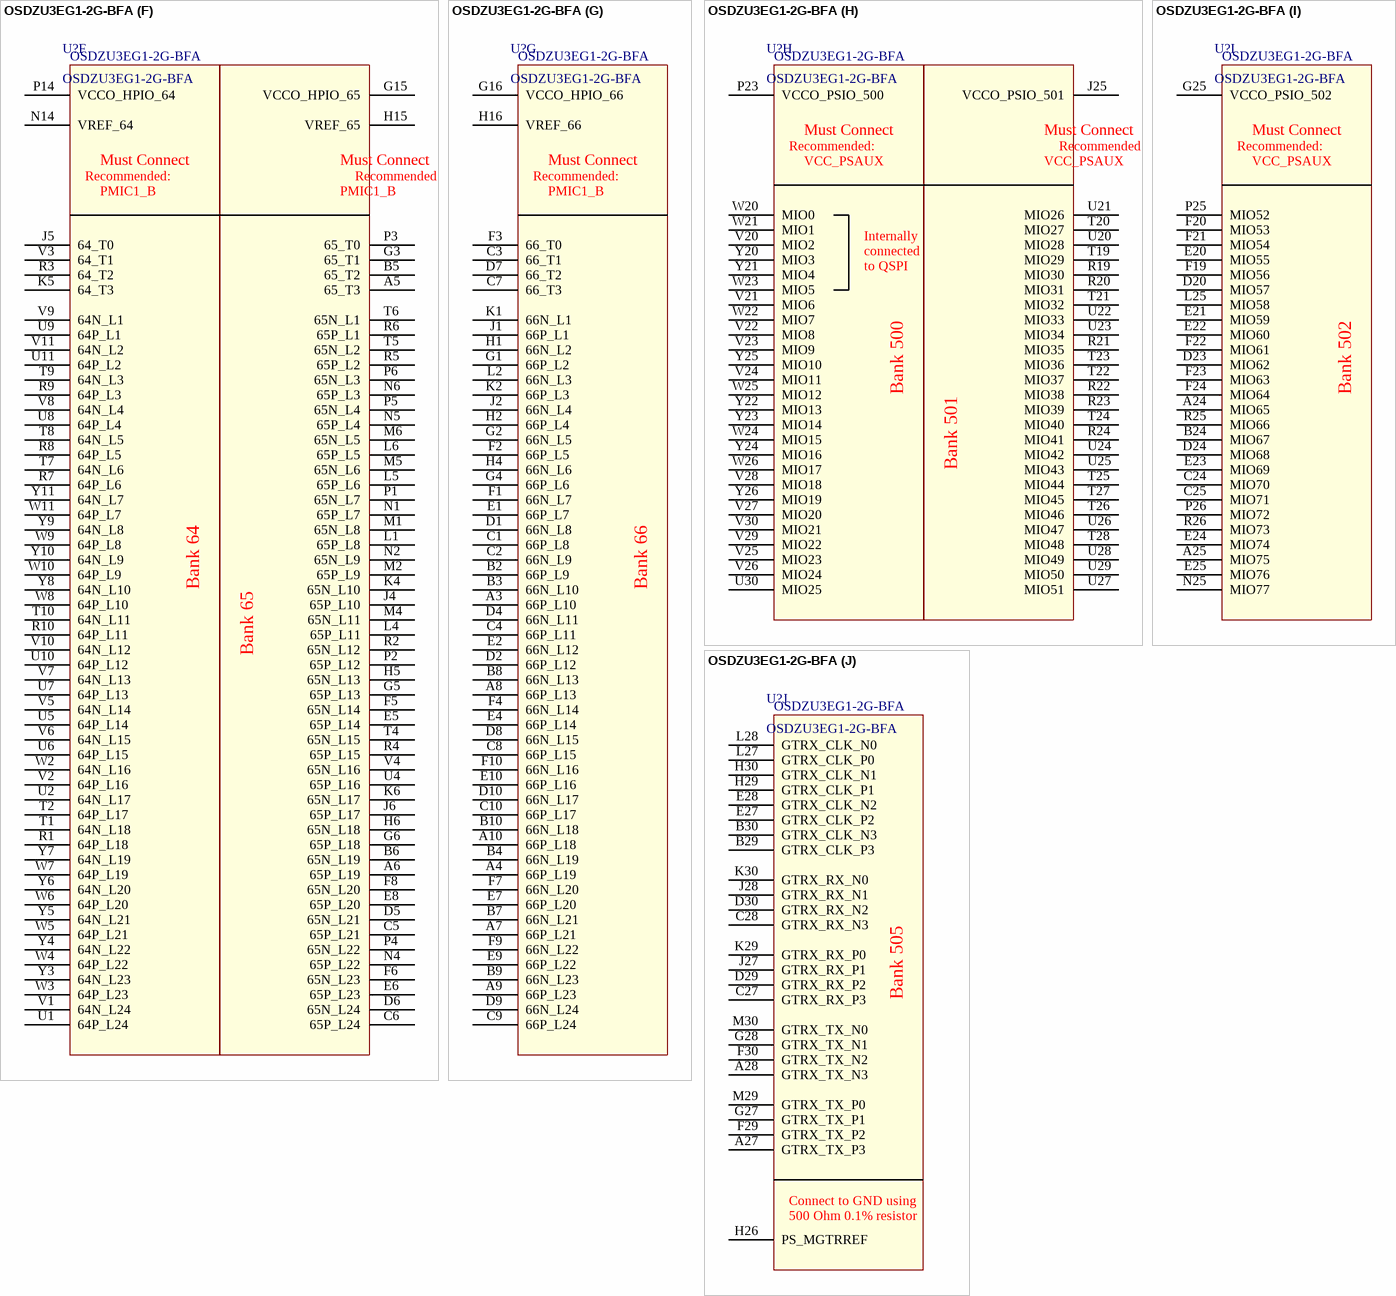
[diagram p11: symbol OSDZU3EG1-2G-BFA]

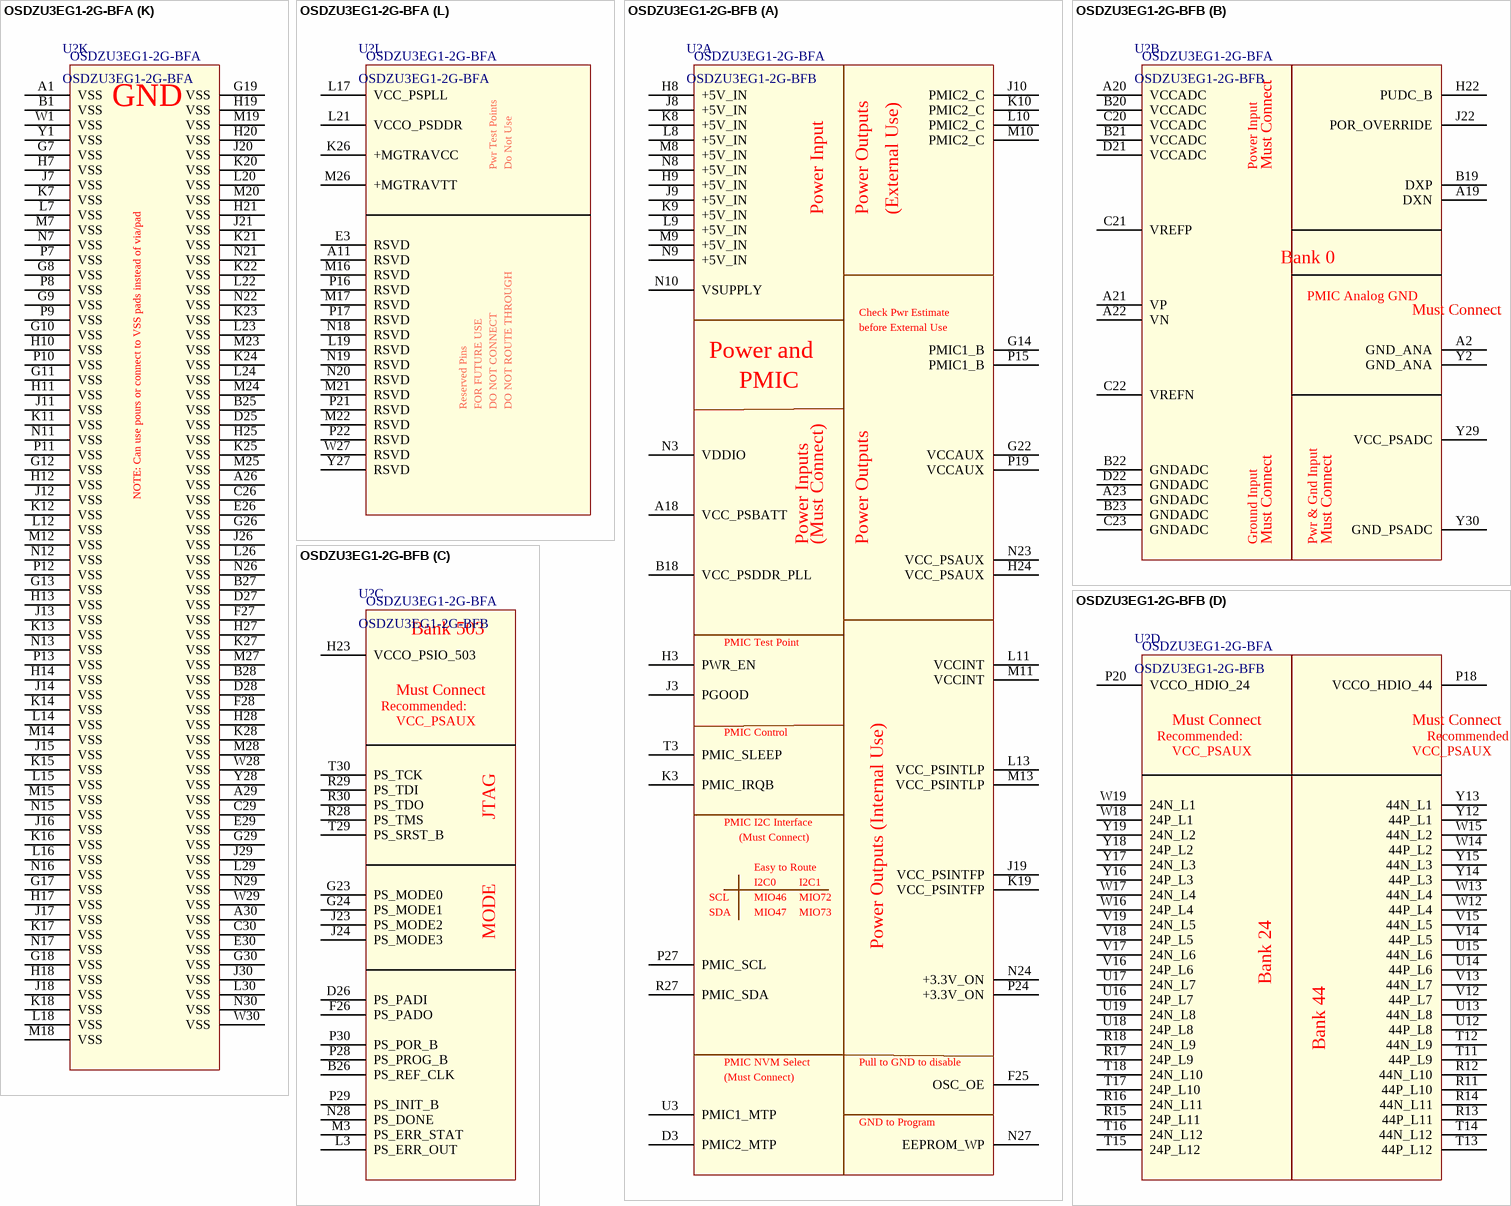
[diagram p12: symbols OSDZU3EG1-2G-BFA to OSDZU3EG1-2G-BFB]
